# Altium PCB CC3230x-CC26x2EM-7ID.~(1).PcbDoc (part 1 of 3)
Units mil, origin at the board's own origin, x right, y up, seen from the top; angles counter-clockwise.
Board outline 2700 x 2300 mil, 4 copper layers (Top Layer, GND, PWR, Bottom Layer), stack 48.84 mil thick; 159 components, 102 nets, 511 pads, 818 vias.
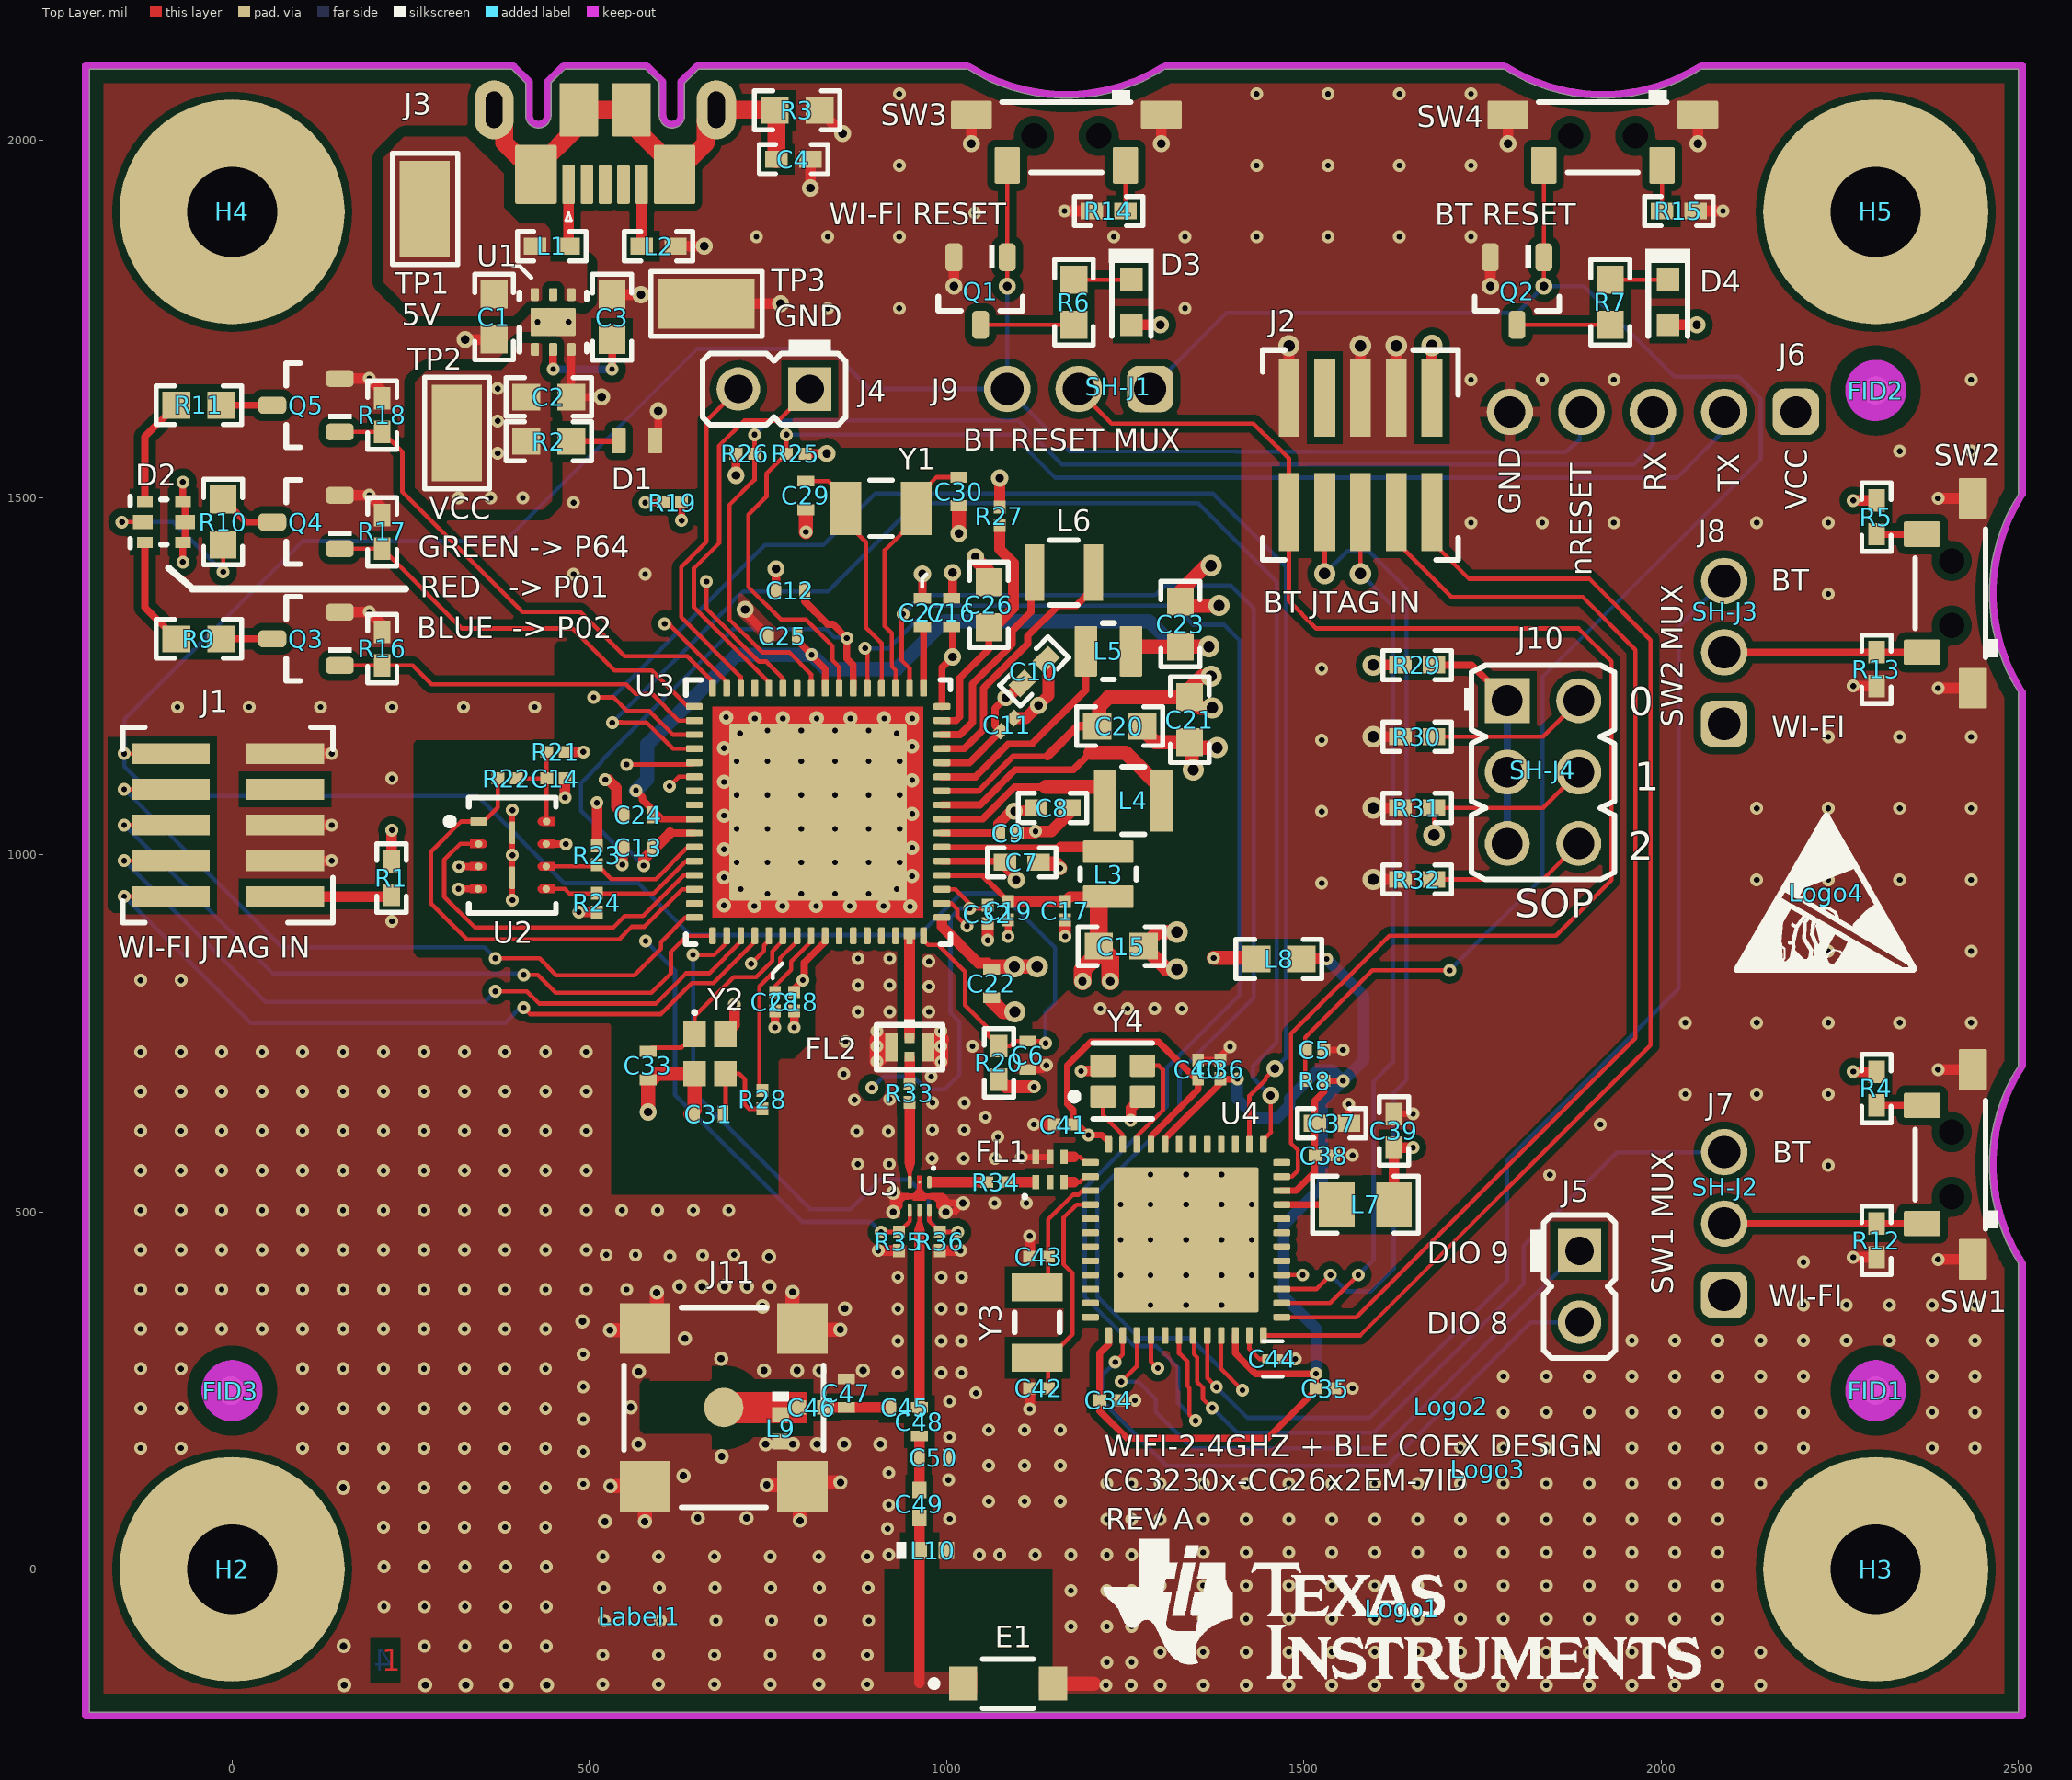
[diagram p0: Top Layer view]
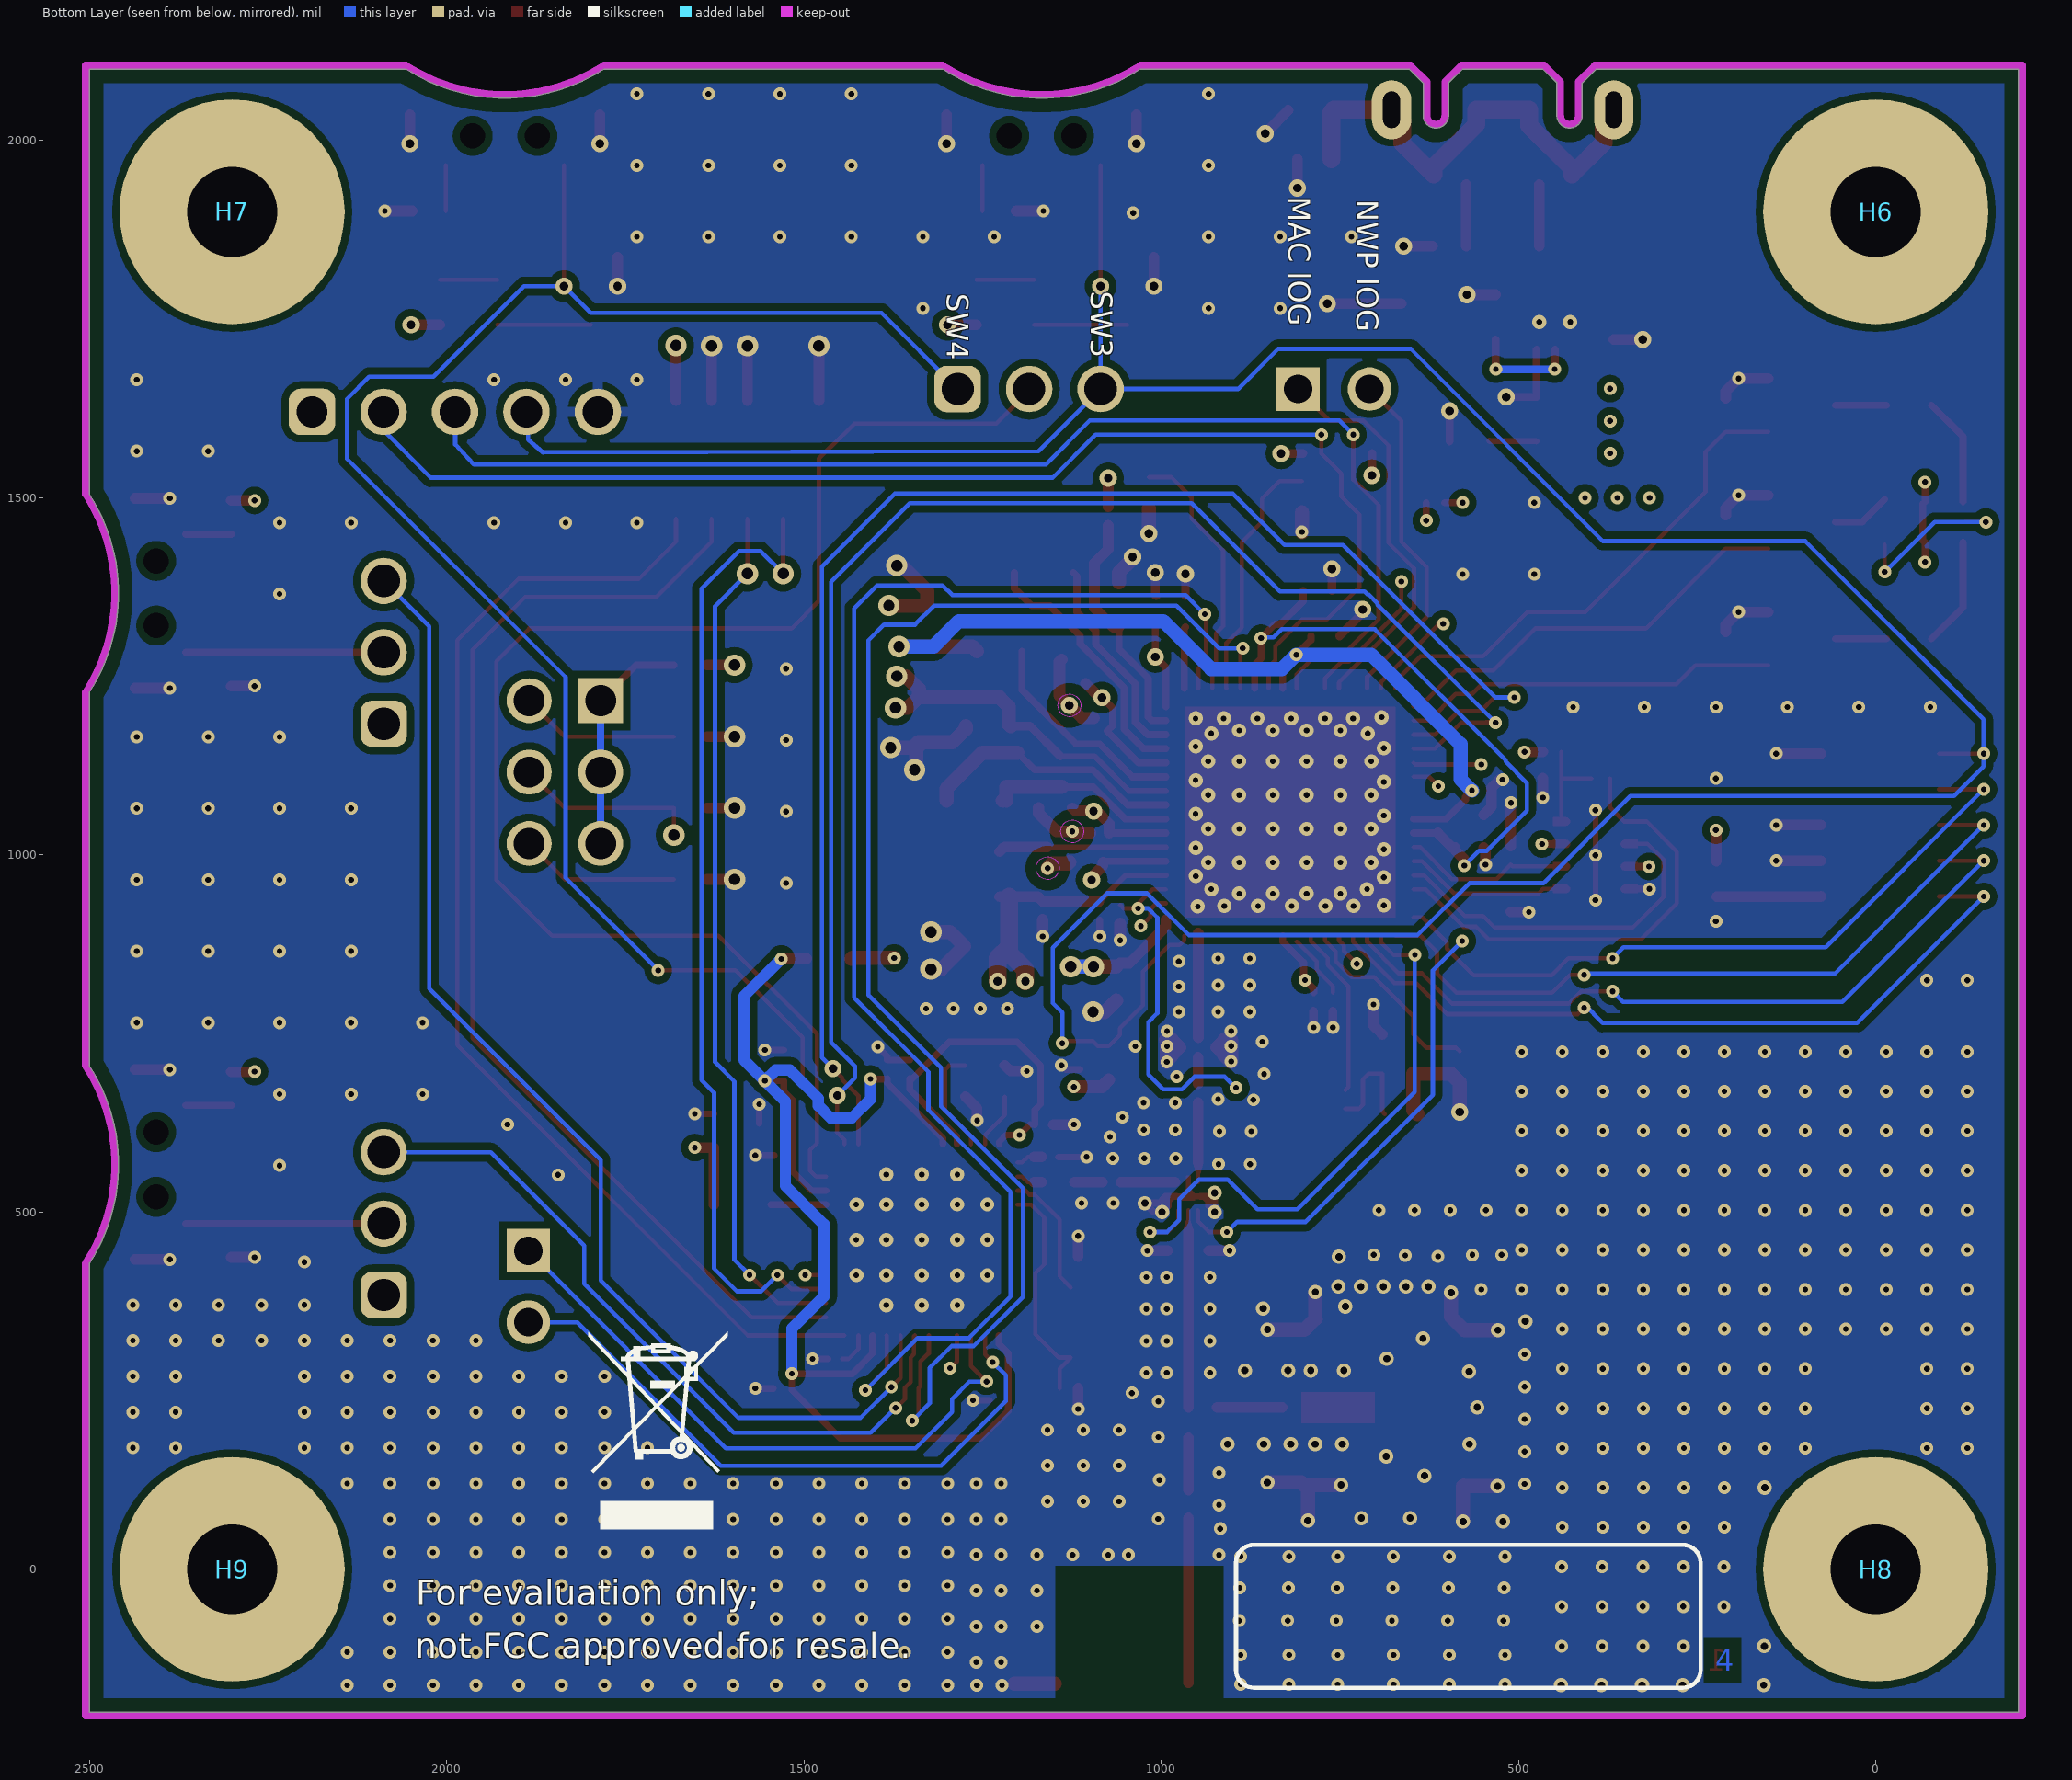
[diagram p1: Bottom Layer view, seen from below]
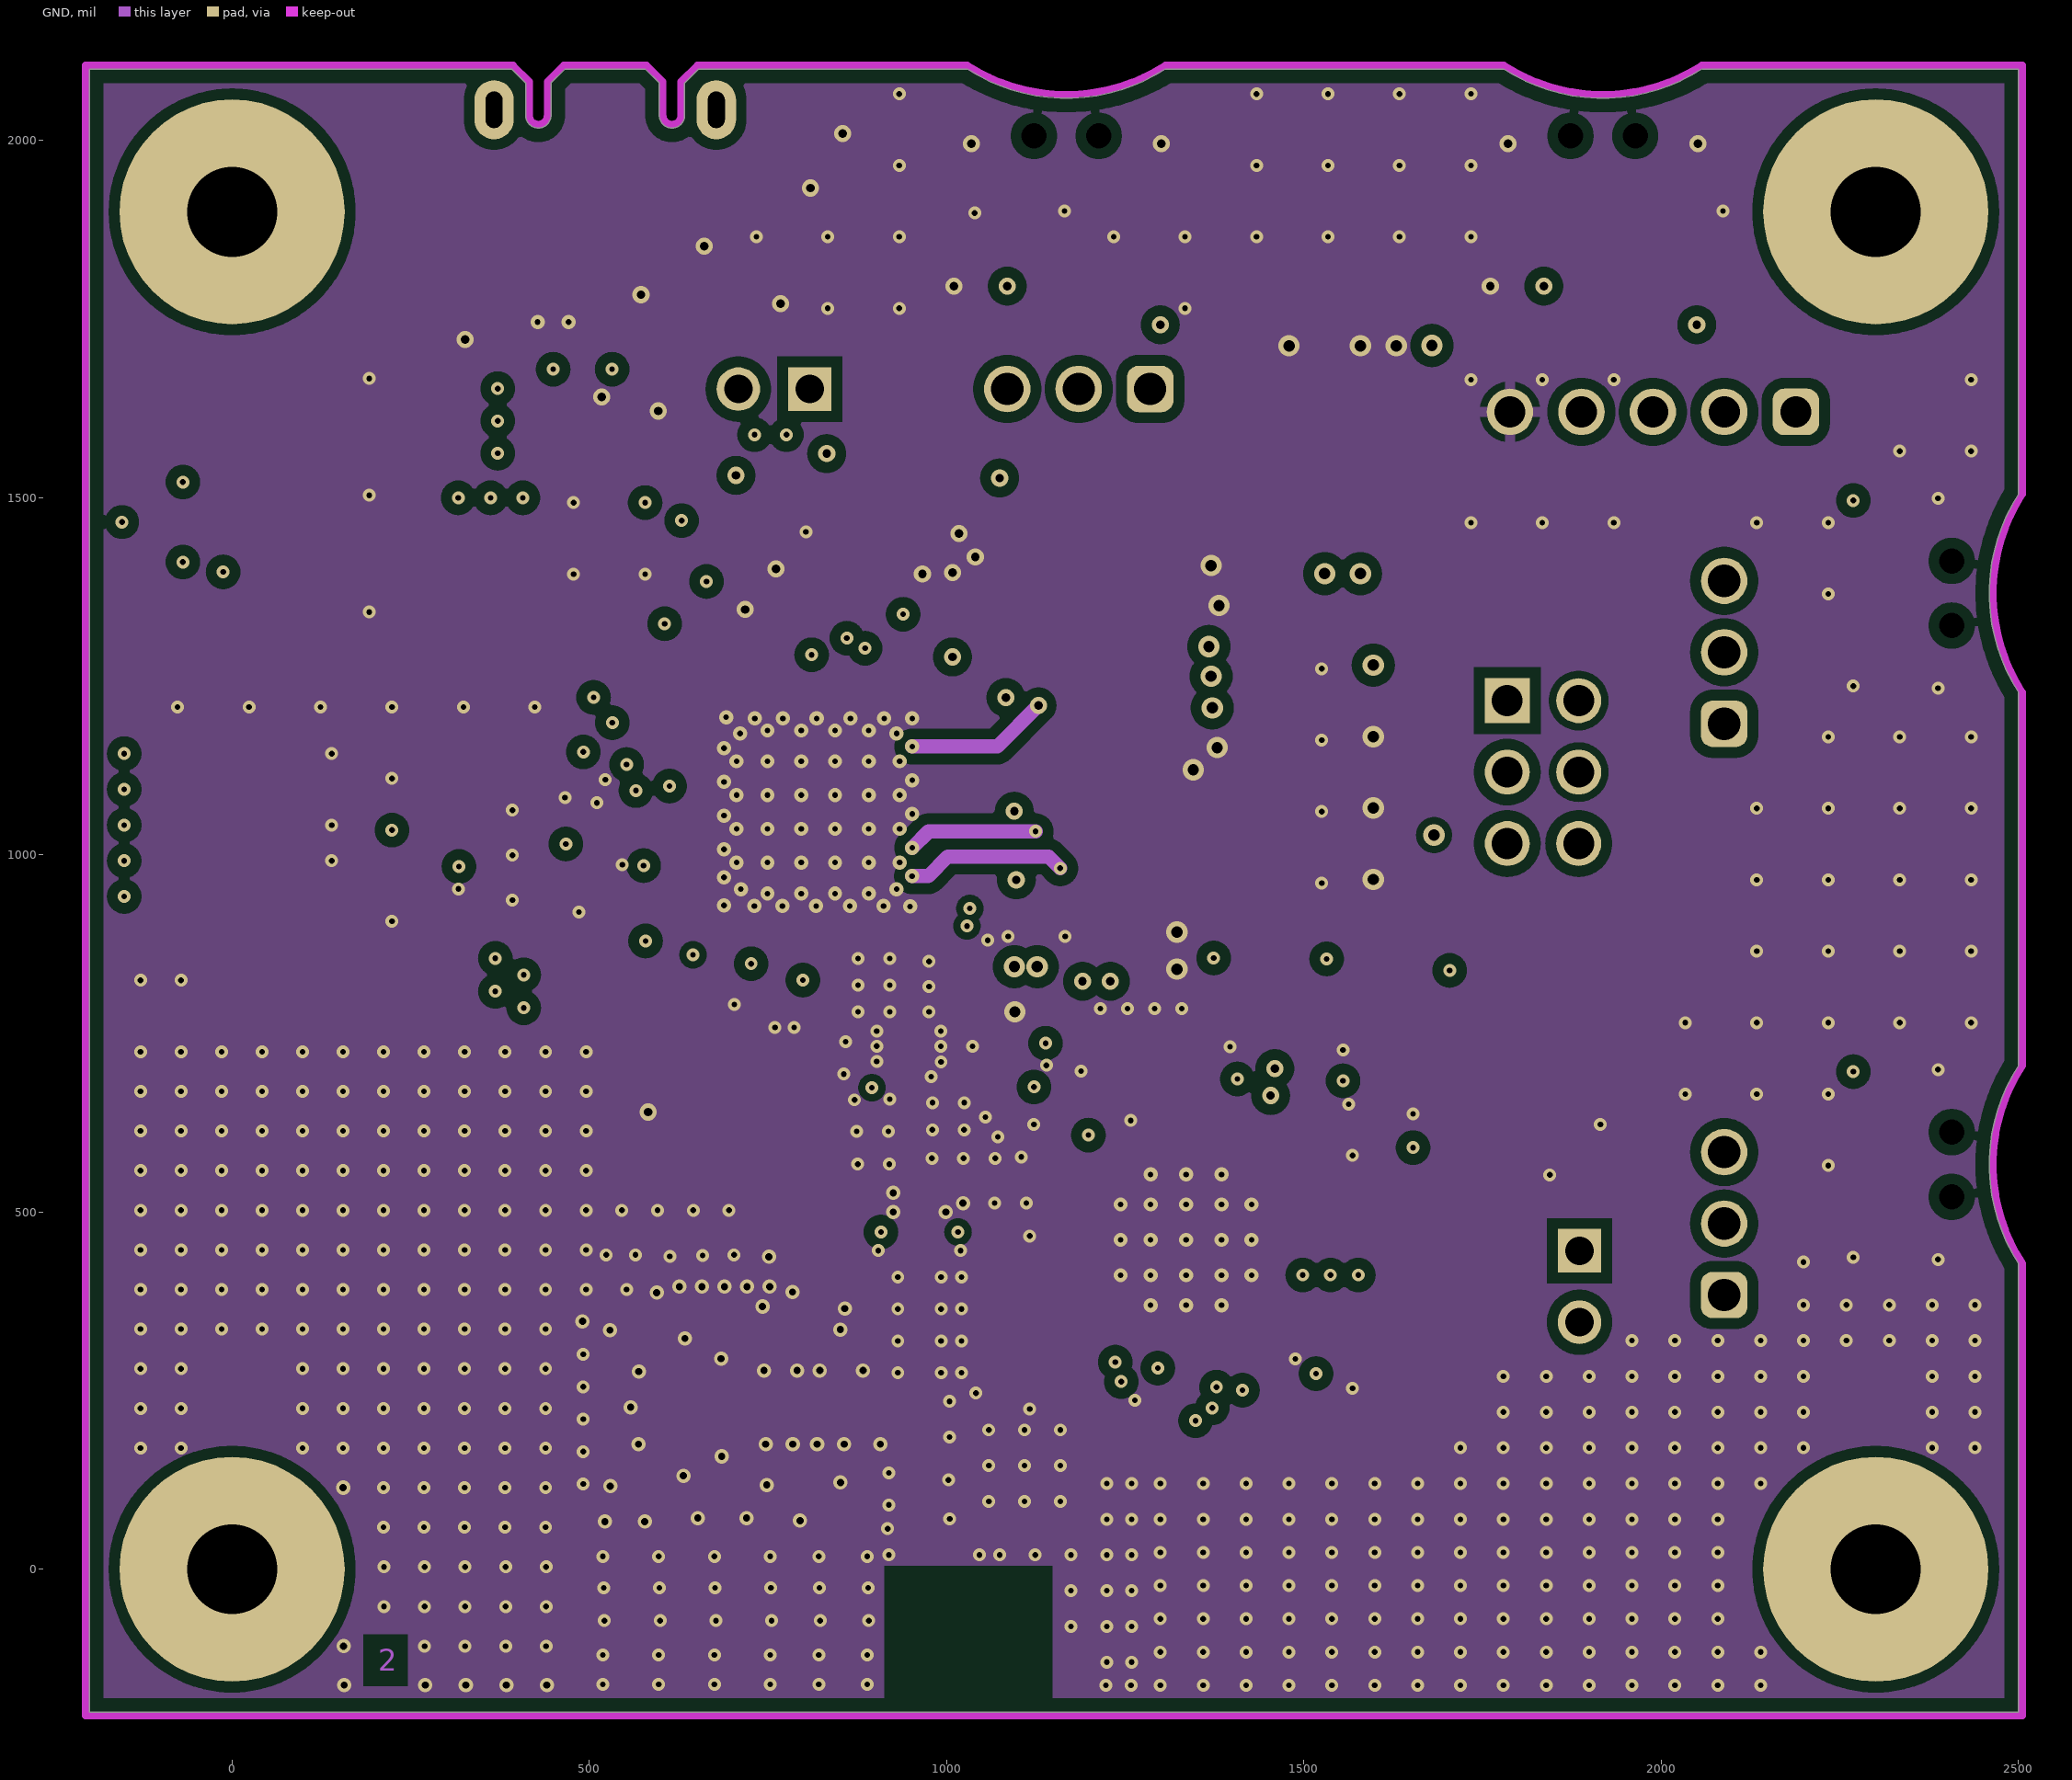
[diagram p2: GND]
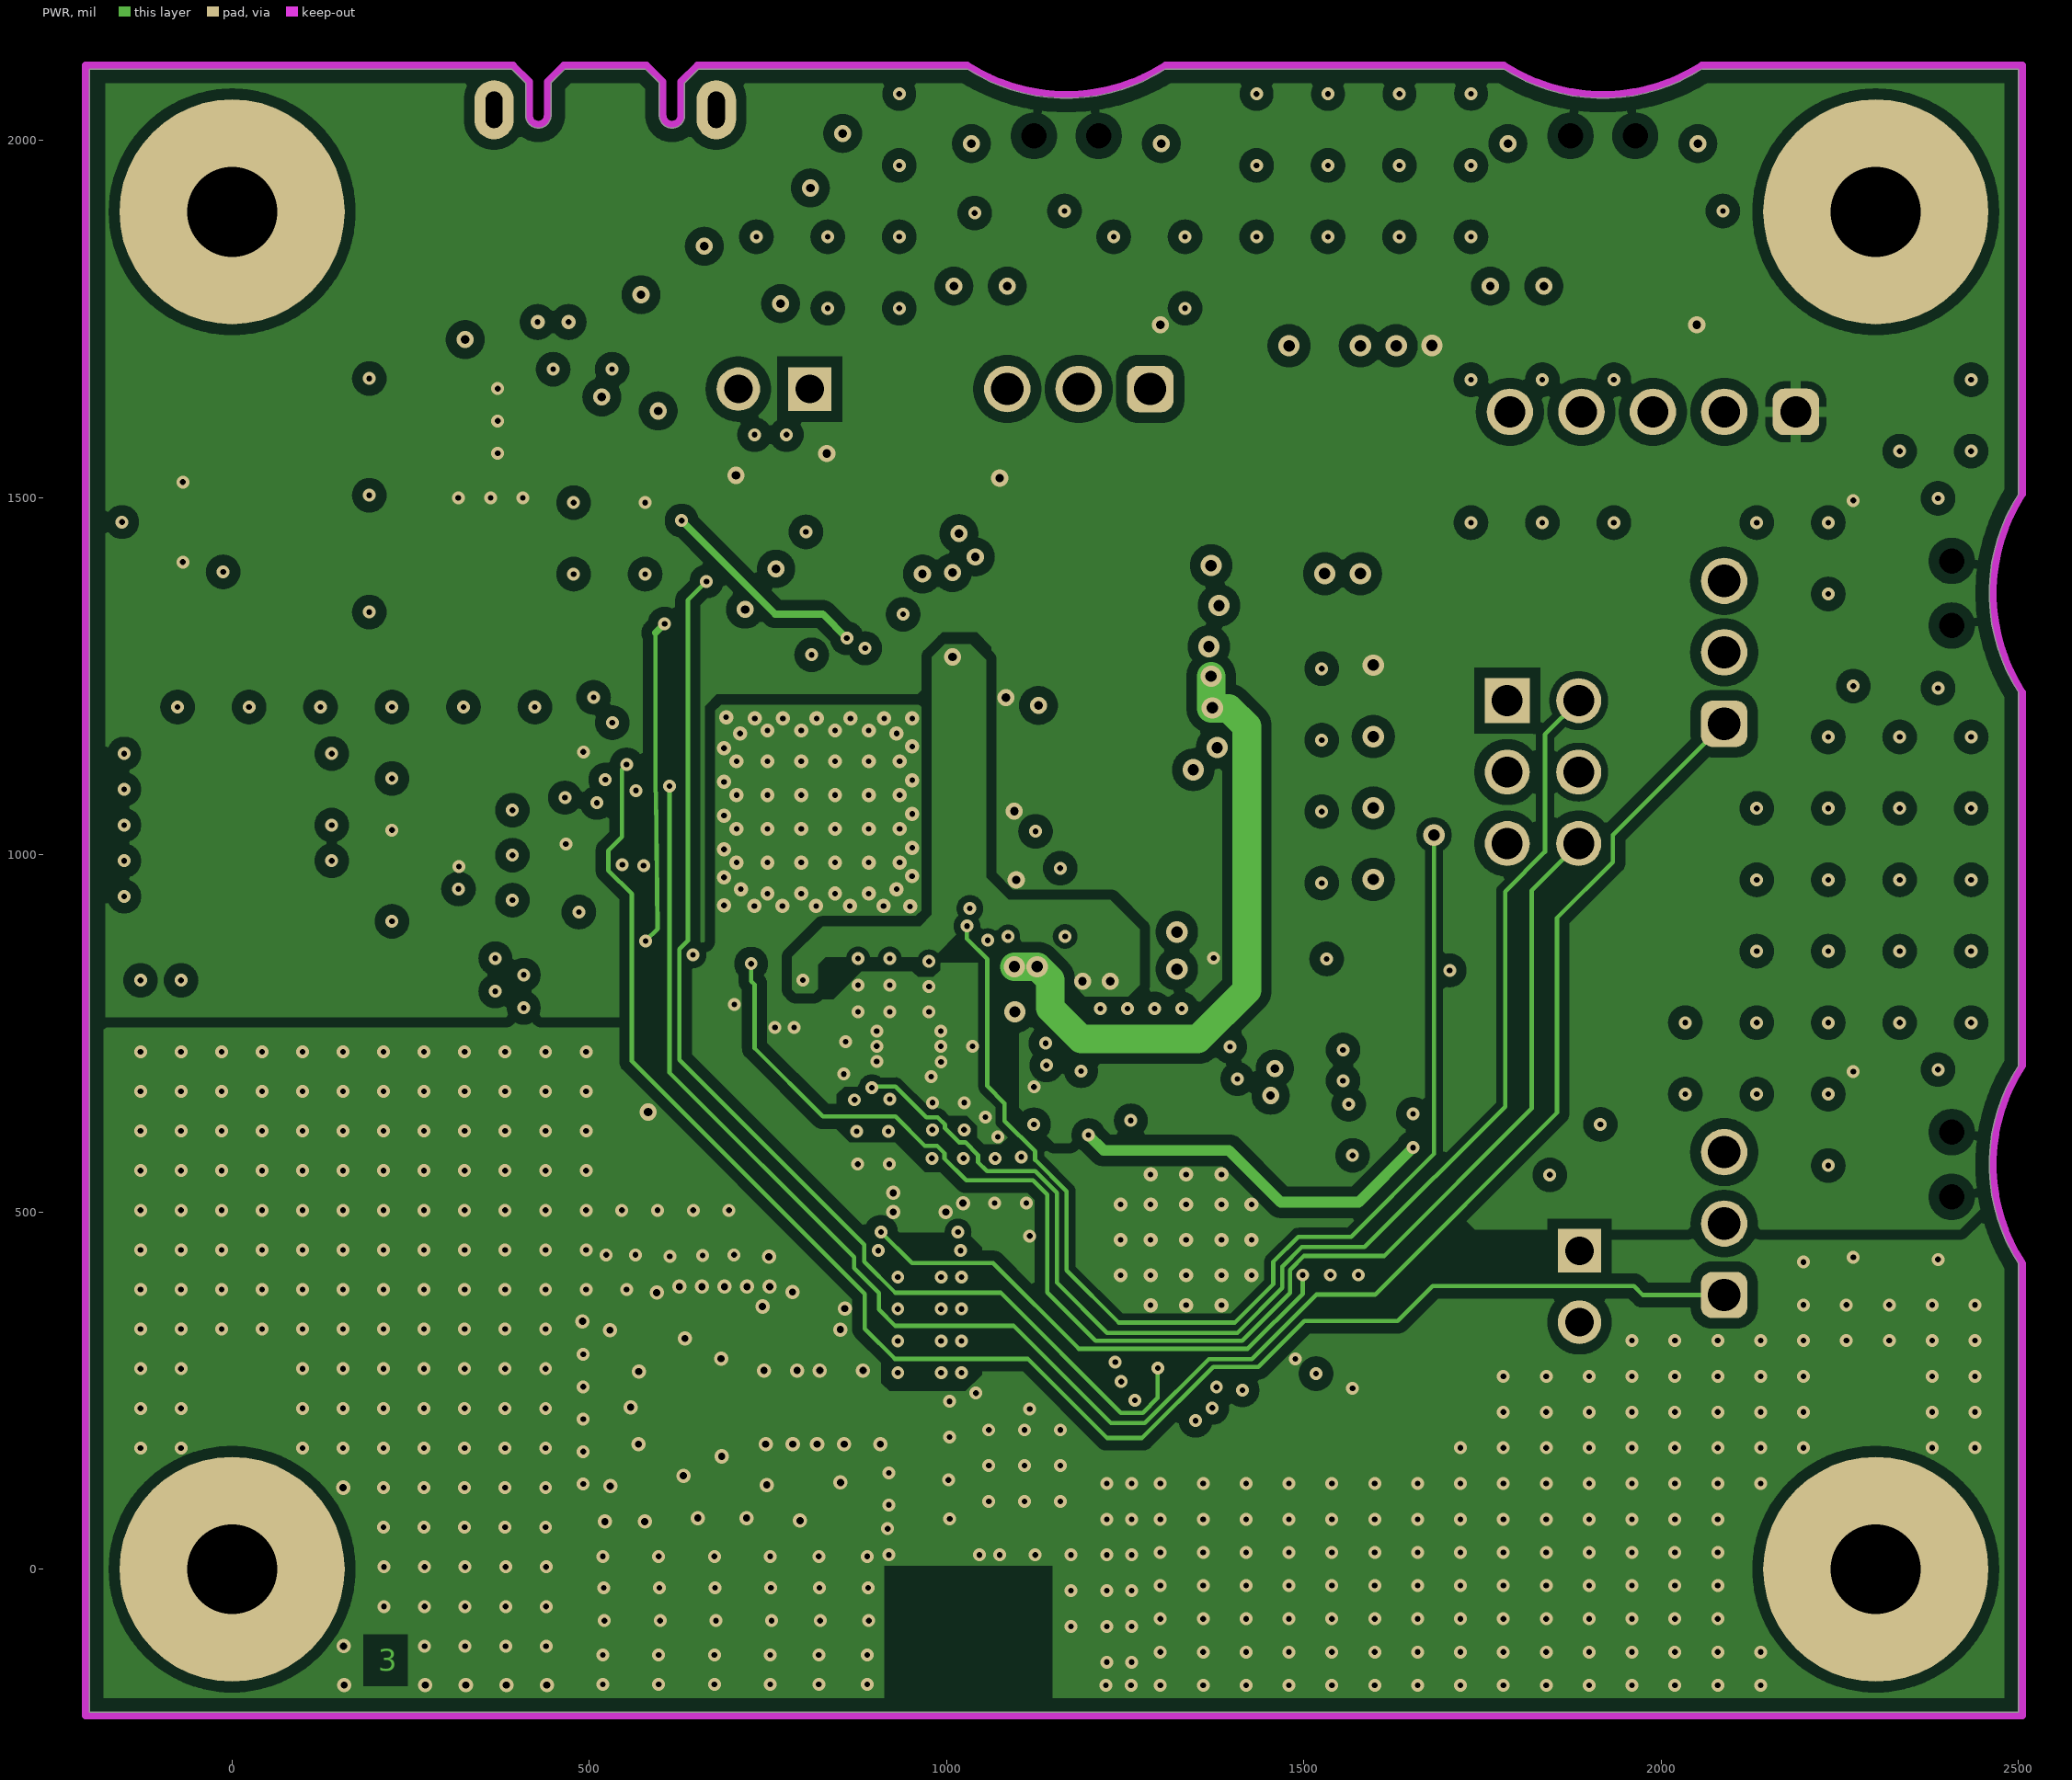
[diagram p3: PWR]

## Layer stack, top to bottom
Top Solder: solder mask 0.8, Solder Resist, Dk 4.1
Top Layer: signal copper 1.69
Dielectric1: core 9.3, FR-4 High Tg, Dk 3.9
GND: signal copper 1.42
Dielectric2: prepreg 24.02, FR-4 High Tg, Dk 4.24
PWR: signal copper 1.42
Dielectric3: core 9.3, FR-4 High Tg, Dk 3.9
Bottom Layer: signal copper 1.69
Bottom Solder: solder mask 0.8, Solder Resist, Dk 4.1

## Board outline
410.78,2035.04 ccw(c428.5,2035.04) 446.21,2035.04 446.21,2080.32 465.9,2100 578.1,2100 597.79,2080.32 597.79,2035.04 ccw(c615.51,2035.04) 633.22,2035.04 633.22,2080.32 652.91,2100 1028.76,2100 ccw(c1167.36,2313.24) 1305.95,2100 1779.55,2100 ccw(c1918.15,2313.24) 2056.74,2100 2500,2100 2500,1504.74 2499.99,1504.74 ccw(c2713.23,1366.14) 2499.99,1227.55 2499.99,705.13 ccw(c2713.23,566.54) 2499.99,427.95 2500,427.95 2500,-200 -200,-200 -200,2100 391.1,2100 410.78,2080.32

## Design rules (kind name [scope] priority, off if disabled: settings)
AcuteAngle [All] p1: minimum=4.50000000000000E+0001 checktracksonly=FALSE
AssemblyTestPointUsage [All] p1: valid=2
Clearance Clearance_BottomKO [iskeepout and OnBottomLayer vs InPoly] p1: gap=15 ignorepadtopadclearanceinfootprint=FALSE
Clearance Clearance_Keepouts [IsKeepOut] p2: gap=20 ignorepadtopadclearanceinfootprint=FALSE
Clearance Clearance_Via_Room [WithinRoom('RoomVia') and IsVia vs inpoly] p3: gap=6 ignorepadtopadclearanceinfootprint=FALSE
Clearance Clearance_2 [inpoly and OnLayer('PWR') and InNet('VDD_ANA') vs isvia and InNet('GND')] p4: gap=8 ignorepadtopadclearanceinfootprint=FALSE
Clearance Clearance_1 [InNet('WiFi_P18_GPIO_28') or InNet('WiFi_P15_GPIO_22') or InNet('WiFi_P34_SOP1') or InNet('WiFi_P35_SOP0') vs Inpoly] p5: gap=10 ignorepadtopadclearanceinfootprint=FALSE
Clearance Clearance_gnd [(OnLayer('gnd') or OnLayer('PWR')) AND INPOLY] p6: gap=15 ignorepadtopadclearanceinfootprint=FALSE
Clearance Clearance_Poly2Poly [InPolygon vs InPolygon] p7: gap=15 ignorepadtopadclearanceinfootprint=FALSE
Clearance Clearance_Poly_All [InPolygon] p8: gap=10 ignorepadtopadclearanceinfootprint=FALSE
Clearance [All] p9: gap=5.9 ignorepadtopadclearanceinfootprint=FALSE except(0: Arc-Hole Track-Hole SMDPad-Hole THPad-Hole Via-Hole Fill-Hole Poly-Hole Region-Hole Text-Hole; 3.9: Arc-SMDPad Track-SMDPad; 4.8: Arc-Fill Arc-Poly Arc-Region Track-Fill Track-Poly Track-Region SMDPad-Fill SMDPad-Poly SMDPad-Region; 5: Arc-Arc Arc-Track Track-Track; 5.6: Arc-Via Track-Via; 6.8: Via-Via; 7: Arc-THPad Track-THPad SMDPad-SMDPad SMDPad-THPad SMDPad-Via THPad-THPad THPad-Via)
ComponentClearance ComponentClearance_ScrewToNut [(HasFootprint('NY PMS 440 0025 PH')) vs (HasFootprint('Keystone_1902C'))] p1: gap=5 collisioncheckmode=3 verticalgap=10 showdistances=FALSE
ComponentClearance [All] p2: gap=10 collisioncheckmode=3 verticalgap=10 showdistances=FALSE
DiffPairsRouting [All] p1: maxlimit=100 minlimit=10 mostfreqgap=10 toplayer_minwidth=15 toplayer_maxwidth=15 toplayer_prefwidth=15 midlayer1_minwidth=15 midlayer1_maxwidth=15 midlayer1_prefwidth=15 midlayer2_minwidth=15 midlayer2_maxwidth=15 midlayer2_prefwidth=15 bottomlayer_minwidth=15 bottomlayer_maxwidth=15 bottomlayer_prefwidth=15 maxuncoupledlength=1000
FabricationTestPointUsage TestPointUsage [All] p1: valid=2 allowmultiple=FALSE
FabricationTestpoint Testpoint [All] p1: side=3 testpointundercomponent=TRUE minsize=40 maxsize=100 preferedsize=60 minholesize=0 maxholesize=40 preferedholesize=32 testpointgrid=1 allowsidetop=TRUE allowsidebottom=TRUE usegrid=TRUE gridtolerance=0.01
FanoutControl Fanout_LCC [IsLCC] p1: bgadir=Out bgaviamode=Centered fanoutstyle=Auto fanoutdirection=Alternating viagrid=1 // Fanout_LCC (Default Rule)
FanoutControl Fanout_BGA [IsBGA] p2: bgadir=Out bgaviamode=Centered fanoutstyle=Auto fanoutdirection=Alternating viagrid=1 // Fanout_BGA (Default Rule)
FanoutControl Fanout_Default [All] p4: bgadir=Out bgaviamode=Centered fanoutstyle=Auto fanoutdirection=Alternating viagrid=1 // Fanout_Default (Default Rule)
FanoutControl Fanout_Small [(CompPinCount < 5)] p5: bgadir=Out bgaviamode=Centered fanoutstyle=Auto fanoutdirection=OutThenIn viagrid=1 // Fanout_Small (Default Rule)
HoleSize [All] p1: absolutevalues=TRUE maxlimit=251 minlimit=7.87 maxpercent=80.000 minpercent=20.000
MinimumAnnularRing MinimumAnnularRing_ThermalPadVias [IsVia] p1: minimumring=5
MinimumAnnularRing [All] p2: minimumring=7.5
MinimumSolderMaskSliver MinimumSolderMaskSliver_Logo [InComponentClass('Logo') vs InComponentClass('Logo')] p1: minsoldermaskwidth=0.7
MinimumSolderMaskSliver [All] p2: minsoldermaskwidth=3
PlaneConnect [All] p1: planeconnectstyle=Relief reliefexpansion=10 reliefentries=4 reliefconductorwidth=10 reliefairgap=10
PolygonConnect [All] p1: thpad.connectstyle=Relief thpad.reliefconductorwidth=15 thpad.reliefentries=4 thpad.polygonreliefangle="90 Angle" thpad.airgapwidth=10 smdpad.connectstyle=Direct smdpad.reliefconductorwidth=10 smdpad.reliefentries=4 smdpad.polygonreliefangle="90 Angle" smdpad.airgapwidth=10 via.connectstyle=Direct via.reliefconductorwidth=10 via.reliefentries=4 via.polygonreliefangle="90 Angle" via.airgapwidth=10
RoomDefinition COEX_Power_Reset_Interfaces [InComponentClass('COEX_Power_Reset_Interfaces')] p1: confinementstyle=ConfineIn formatcopy=TRUE lockcomponents=FALSE outline 634.22,901.6 986.77,901.6 986.77,657 634.22,657
RoutingVias ThermalPadVias [IsVia and InAnyComponent] p1: holewidth=7.87 width=19.68 viastyle="Through Hole" minholewidth=7.87 minwidth=19.68 maxholewidth=12.99 maxwidth=23.62
RoutingVias [All] p2: holewidth=16 width=34 viastyle="Through Hole" minholewidth=7.87 minwidth=18 maxholewidth=40 maxwidth=65
SilkToBoardRegionClearance [Not ((IsComment or IsDesignator) And (Hide <> 'False')) and not InRegion(1000,500,4000,800)] p1:
SilkToSilkClearance SilkToSilkClearance_Pb-FreeLogo [(HasFootprint('Pb-Free_Overlay_Medium') OR HasFootprint('Pb-Free_Overlay_Small')) vs (HasFootprint('Pb-Free_Overlay_Medium') OR HasFootprint('Pb-Free_Overlay_Small'))] p1: silktosilkclearance=0
SilkToSilkClearance [All] p2: silktosilkclearance=4
SilkToSolderMaskClearance SilkToComonentPadClearance [IsPad and InAnycomponent] p1: minsilkscreentomaskgap=5 clearancetoexposedcopper=TRUE
SilkToSolderMaskClearance "Silk to Solder Mask Opening" [All] p2: minsilkscreentomaskgap=4 clearancetoexposedcopper=FALSE
SolderMaskExpansion [All] p1: expansion=0
Width [All] p1: maxlimit=100 minlimit=5.9 preferedwidth=10 minimp=50.000000 maximp=50.000000 favimp=50.000000 checkconnectedcopper=TRUE
15 further rules are at their usual default settings.

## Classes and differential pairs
component class Logo: Logo2
component class Label: Label1
component class AssemblyNote: ZZ1 ZZ2 ZZ3 ZZ4
component class FiducialMark: FID1 FID2 FID3
component class COEX_Hardware: FID1 FID2 FID3 H2 H3 H4 H5 H6 H7 H8 H9 Label1 Logo1 Logo2 Logo3 Logo4 SH-J1 SH-J2 SH-J3 SH-J4 ZZ1 ZZ2 ZZ3 ZZ4
component class "Mounting Holes": H1 H2 H3 H4 H5
component class Header: J4 J5 J6 J8 J9 J10
component class COEX_Power_Reset_Interfaces: C1 C2 C3 C4 C5 D1 D2 D3 D4 J1 J2 J3 J4 J5 J6 J9 J10 L1 L2 Q1 Q2 Q3 Q4 Q5 R2 R3 R4 R5 R6 R7 R8 R10 R11 R12 R16 R17 R18 R35 SW1 SW2 SW3 SW4 TP1 TP2 TP3 U1
component class COEX_CC3230S_EngineArea: C6 C7 C8 C9 C10 C11 C12 C13 C14 C15 C16 C17 C18 C19 C20 C21 C22 C23 C24 C25 C26 C27 C28 C29 C30 C31 C32 C33 J10 L3 L4 L5 L6 R17 R19 R20 R21 R23 R24 R25 R26 R27 R28 R29 R30 R31 R32 U2 U3 Y1 Y2
component class COEX_CC2642R_EngineArea: C5 C34 C35 C36 C37 C38 C39 C40 C41 C42 C44 FL1 L7 L8 R? U4 Y3 Y4
component class COEX_AntennaRFSection: C45 C46 C47 C48 C49 C50 E1 FL2 J10 L9 L10 R8 R33 R35 R36 U5
component class Shunt: SH-J1 SH-J2 SH-J3 SH-J4

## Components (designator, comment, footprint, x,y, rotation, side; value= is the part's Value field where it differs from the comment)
C1 "GRM188R71E105KA12D" 0603 366.53,1752.71 r270 top value=1uF
C2 "GRM188R71E105KA12D" 0603 443.26,1640.84 r0 top value=1uF
C3 "06031C102JAT2A" 0603 531.79,1752.52 r90 top locked value=1000pF
C4 "C1005X7R1C103K050BA" 0402 785.5,1973.8 r0 top locked value=0.01uF
C5 "GRM033Z71C104KE14D" 0201 1514.87,726.94 r0 top value=0.1uF
C6 "0402B103K500CT" 0402S 1113.53,719.34 r270 top value=0.01uF
C7 "CMP-0064972-2" 0402 1105,989.5 r0 top locked value=4.7uF
C8 "CMP-0064972-2" 0402 1147.91,1065.69 r0 top locked value=4.7uF
C9 "GJM0335C1ER60BB01D" 0201_033 1085.79,1030.47 r0 top locked value=0.6pF
C10 "CMP-0064972-2" 0402 1122.32,1256.71 r45 top locked value=4.7uF
C11 "GJM0335C1ER50BB01D" 0201_033 1084.87,1182.18 r45 top locked value=0.5pF
C12 "CL05B104KO5NNNC" 0402S 781.16,1369.99 r180 top locked value=0.1uF
C13 "CL05B104KO5NNNC" 0402S 568.62,1010 r180 top locked value=0.1uF
C14 "GRM033Z71C104KE14D" 0201 453.03,1107.03 r0 top value=0.1uF
C15 "CMP-0064953-4" 0603 1244,872 r0 top locked value=10uF
C16 "CL05B104KO5NNNC" 0402S 1007,1339 r90 top locked value=0.1uF
C17 "GJM0335C1ER20BB01D" 0201_033 1165.68,921.74 r270 top locked value=0.2pF
C18 "CL03A104KP3NNNC" 0201 786.58,794.26 r270 top value=0.1uF
C19 "GJM0335C1ER60BB01D" 0201_033 1085.88,921.74 r270 top locked value=0.6pF
C20 "CMP-0064952-4" 0603 1242,1180 r0 top locked value=22uF
C21 "CMP-0064952-4" 0603 1340,1189 r270 top locked value=22uF
C22 "CL05A105MP5NNNC" 0402S 1062.64,819.79 r270 top locked value=1uF
C23 "CMP-0064953-4" 0603 1327,1323 r90 top locked value=10uF
C24 "CL05B104KO5NNNC" 0402S 568.62,1056 r180 top locked value=0.1uF
C25 "CL05B104KO5NNNC" 0402S 770.4,1306.4 r180 top locked value=0.1uF
C26 "CMP-0064953-4" 0603 1059,1350 r90 top locked value=10uF
C27 "CL05B104KO5NNNC" 0402S 966,1339 r90 top locked value=0.1uF
C28 "CMP-0009655-3" 0201 759.69,794.26 r270 top value=0.1uF
C29 "0402N100J500CT" 0402S 803,1502.95 r270 top locked value=10pF
C30 "0402N100J500CT" 0402S 1016.97,1508.62 r270 top locked value=10pF
C31 "0402N6R2C500CT" 0402S 666.89,637 r180 top locked value=6.2pF
C32 "GJM0335C1ER60BB01D" 0201_033 1057.24,916.74 r270 top value=0.6pF
C33 "0402N6R2C500CT" 0402S 582.17,705 r270 top locked value=6.2pF
C34 "GRM033Z71C104KE14D" 0201 1227.13,236.52 r0 top value=0.1uF
C35 "GRM033Z71C104KE14D" 0201 1529.82,253.06 r0 top value=0.1uF
C36 "GRM033Z71C104KE14D" 0201 1383.14,699.65 r90 top locked value=0.1uF
C37 "GRM155R60J226ME11D" 0402 1538.87,624.2 r0 top value=22uF
C38 "GRM033Z71C104KE14D" 0201 1528.24,579.25 r0 top value=0.1uF
C39 "GRM155R60J226ME11D" 0402 1625.87,613.75 r90 top value=22uF
C40 "GRM033Z71C104KE14D" 0201 1351.65,699.65 r90 top locked value=0.1uF
C41 "GRM033Z71C104KE14D" 0201 1163.84,622.46 r180 top locked value=0.1uF
C42 "C0603C0G1E120J030BA" 0201_033 1129.12,253.28 r180 top value=12pF
C43 "C0603C0G1E120J030BA" 0201_033 1129.12,437.63 r180 top value=12pF
C44 "JMK063BC6105MP-F" FP-JMK063BC6105MP-F_0201-MFG 1456.21,294.44 r180 top
C45 "CMP-0006495-2" 0402S 941.85,226.53 r180 top locked value=8.2pF
C46 "CMP-0006447-2" 0402L 811.01,226.4 r180 top value=2.2pF
C47 "CMP-0006426-2" 0402S 859.44,246.4 r90 top value=1pF
C48 "CMP-0006495-2" 0402S 961.85,206.53 r270 top locked value=8.2pF
C49 "CMP-0006447-2" 0402L 961.85,91.39 r270 top value=2.2pF
C50 "CMP-0006426-2" 0402S 981.85,156.39 r0 top value=1pF
D1 "19-217/R6C-AL1M2VY/3T" 19-217_R6C-AL1M2VY_3T_Red 566.46,1579.57 r0 top locked value=Red
D2 "EAST1616RGBA8" EAST1616_RGB -95.52,1465.84 r270 top value=RGB
D3 "150060YS75000" WL-SMCW_YELLOW 1258.42,1773.44 r270 top locked value=Yellow
D4 "150060YS75000" WL-SMCW_YELLOW 2009.21,1773.44 r270 top locked value=Yellow
E1 "AH316M245001-T" TAYO_AH316M 1085.71,-160 r0 top
FID1 "CMP-0077181-1" Fiducial10-20#1 2300,250 r90 top
FID2 "CMP-0077181-1" Fiducial10-20#1 2300,1650 r270 top
FID3 "CMP-0077181-1" Fiducial10-20#2 0,250 r90 top
FL1 "2450BM14G0011" Johanson_2450BM14G0011 1144.47,559.49 r90 top locked
FL2 "CMP-0002039-2" TDK_DEA202450BT-1294C1-H 948.07,730.46 r0 top value="1.02 dB"
H2 "NY PMS 440 0025 PH" "NY PMS 440 0025 PH" 0,0 r180 top locked
H3 "NY PMS 440 0025 PH" "NY PMS 440 0025 PH" 2300,0 r180 top locked
H4 "NY PMS 440 0025 PH" "NY PMS 440 0025 PH" 0,1900 r180 top locked
H5 "NY PMS 440 0025 PH" "NY PMS 440 0025 PH" 2300,1900 r180 top locked
H6 "Nut" Keystone_1902C 0,1900 r0 bottom locked
H7 "Nut" Keystone_1902C 2300,1900 r0 bottom locked
H8 "Nut" Keystone_1902C 0,0 r0 bottom locked
H9 "Nut" Keystone_1902C 2300,0 r0 bottom locked
J1 "FTSH-105-01-F-DV-K" Samtec_FTSH-105-01-x-DV-K -6.04,1041.65 r180 top locked
J2 "FTSH-105-01-F-DV-K" Samtec_FTSH-105-01-x-DV-K 1578.93,1559.75 r270 top
J3 "1051640001" Molex_1051640001 522,2100 r180 top
J4 "GBC02SAAN" Sullins_Gxx02SAAN 758.31,1651.91 r180 top locked
J5 "GBC02SAAN" Sullins_Gxx02SAAN 1885.45,395.74 r270 top
J6 "61300511121" Wurth_61300511121 1988.12,1620 r180 top
J7 "61300311121" WURTH_61300311121 2087.92,483.86 r90 top
J8 "61300311121" WURTH_61300311121 2087.92,1283.47 r90 top
J9 "61300311121" WURTH_61300311121 1184.68,1652.09 r180 top
J10 "61300621121" Wurth_61300621121 1834.35,1115.81 r0 top
J11 "CMP-0055832-1" Hustsan_SMA-10V21-TGG 687.93,226.39 r0 top locked
L1 "CMP-0003309-1" 0402 447.2,1851.8 r180 top value="10 ohm"
L2 "CMP-0003309-1" 0402 596.81,1851.8 r0 top value="10 ohm"
L3 "CMP-0058761-1" LQM2MPN_G0 1226,972.87 r90 top locked value=2.2uH
L4 "CMP-0058750-1" 1008 1261,1076 r180 top locked value=1uH
L5 "CMP-0058761-1" LQM2MPN_G0 1226.13,1285 r180 top locked value=2.2uH
L6 "CMP-0062710-1" MLP2520S-M 1164,1395 r0 top locked value=10uH
L7 "MLZ2012N6R8LT000" 0805_HV 1585.87,510.28 r0 top value=6.8uH
L8 "BLM18HE152SN1D" 0603 1464.74,854.35 r0 top value="1500 ohm"
L9 "LQG15HS3N9S02D" IND_LQG15H 767.58,197.44 r270 top value=3.9nH
L10 "LQG15HS3N9S02D" IND_LQG15H 980.55,26.39 r0 top value=3.9nH
Label1 "CMP-0003625-1" Label_650x200 570.15,-65.85 r0 top
Logo1 "Texas Instruments" TI_Stacked_Overlay_Small 1637.53,-55.51 r0 top
Logo2 "WEEE logo" WEEE_Minimum 1705.88,228.42 r180 top
Logo3 "FCC disclaimer" FCC_disclaimer_stacked 1756.84,140.19 r180 top locked
Logo4 "ESD Susceptible" ESD_Overlay_Medium 2230.55,946.28 r0 top
Q1 "CMP-0000755-1" SOT-23 1047.28,1789.18 r270 top value=50V
Q2 "CMP-0000755-1" SOT-23 1798.07,1789.18 r270 top value=50V
Q3 "BSS138" SOT-23 103.29,1302.37 r180 top value=50V
Q4 "BSS138" SOT-23 103.29,1465.84 r180 top value=50V
Q5 "BSS138" SOT-23 103.29,1629.3 r180 top value=50V
R1 "CRCW04021K00JNED" 0402 222.99,967.38 r270 top value=1.0k
R2 "CMP-0025765-4" 0603 443.26,1578.75 r0 top value=270
R3 "CMP-0025698-4" 0603 790.5,2042.15 r180 top locked value=100k
R4 "CMP-0026852-3" 0402 2301.1,672.84 r270 top value=1.0k
R5 "CMP-0026852-3" 0402 2301.1,1472.44 r270 top locked value=1.0k
R6 "CMP-0025765-4" 0603 1177.99,1773.44 r90 top locked value=270
R7 "CMP-0025765-4" 0603 1928.77,1773.44 r90 top locked value=270
R8 "RC0201JR-7D100KL" 0201 1514.87,683.63 r0 top value=100k
R9 "RC0603JR-07750RL" 0603 -46.63,1302.37 r180 top value=750
R10 "RC0603JR-07750RL" 0603 -12.58,1465.84 r270 top value=750
R11 "RC0603JR-07750RL" 0603 -46.63,1629.3 r180 top value=750
R12 "CMP-0026825-5" 0402 2301.1,460.24 r270 top value=10k
R13 "CMP-0026825-5" 0402 2301.1,1259.85 r270 top value=10k
R14 "CMP-0026656-1" 0402 1226.41,1901.11 r0 top locked value=100
R15 "CMP-0026656-1" 0402 2024.44,1901.11 r180 top value=100
R16 "CMP-0026823-3" 0402 209.96,1288.59 r90 top value=100k
R17 "CMP-0026823-3" 0402 209.96,1452.06 r90 top value=100k
R18 "CMP-0026823-3" 0402 209.96,1615.52 r90 top value=100k
R19 "CRCW02010000Z0ED" 0201 616,1492.99 r180 top locked value=0
R20 "CRCW0402100KJNED" 0402 1073.21,708.83 r270 top value=100k
R21 "CRCW02010000Z0ED" 0201 453.03,1144.04 r0 top value=0
R22 "RC0201JR-7D100KL" 0201 384.79,1107.03 r0 top value=100k
R23 "RC0201JR-7D100KL" 0201 510.53,999.28 r270 top value=100k
R24 "RC0201JR-7D100KL" 0201 510.53,933.01 r90 top value=100k
R25 "RC0201JR-7D100KL" 0201 788.68,1561.54 r0 top value=100k
R26 "RC0201JR-7D100KL" 0201 718.01,1561.54 r180 top value=100k
R27 "CRCW02010000Z0ED" 0201 1073.99,1474.02 r90 top locked value=0
R28 "CRCW02010000Z0ED" 0201 742.12,657.4 r90 top locked value=0
R29 "CRCW0402270RJNED" 0402 1658.32,1265.54 r180 top value=270
R30 "CRCW0402100KJNED" 0402 1658.32,1165.54 r0 top value=100k
R31 "CRCW0402100KJNED" 0402 1658.32,1065.54 r0 top value=100k
R32 "CRCW04022K70JNED" 0402 1658.32,965.54 r0 top value=2.7k
R33 "ERJ-1GE0R00C" 0201 948.07,666.37 r90 top value=0
R34 "ERJ-1GE0R00C" 0201 1069.15,541.78 r0 top value=0
R35 "RC0201JR-7D100KL" 0201 933.07,458.99 r90 top value=100k
R36 "RC0201JR-7D100KL" 0201 990.63,458.99 r90 top value=100k
SH-J1 "60900213421" Wurth_60900213421 1240.3,1655.53 r0 top
SH-J2 "60900213421" Wurth_60900213421 2089.67,535.35 r90 top
SH-J3 "60900213421" Wurth_60900213421 2089.68,1341.01 r90 top
SH-J4 "60900213421" Wurth_60900213421 1834.54,1118.82 r0 top
SW1 "CMP-0002328-1" SW_1188E 2392.57,566.54 r180 top
SW2 "CMP-0002328-1" SW_1188E 2392.57,1366.14 r180 top locked
SW3 "CMP-0002328-1" SW_1188E 1167.36,1992.58 r270 top
SW4 "CMP-0002328-1" SW_1188E 1918.15,1992.58 r270 top
TP1 "5015" Testpoint_Keystone_Miniature 269.58,1904.12 r90 top locked
TP2 "5015" Testpoint_Keystone_Miniature 314.28,1590.42 r90 top
TP3 "5015" Testpoint_Keystone_Miniature 663.85,1771.57 r0 top locked
U1 "TPS73733DRVR" DRV0006A 449.17,1745.82 r90 top
U2 "MX25R3235FZBIL0" FP-MX25R3235FZBIL0_USON8-MFG 392.2,999.49 r0 top
U3 "CC3230SM2RGKR" RGK0064B 820,1060 r0 top locked
U4 "CC2642R1FRGZR" RGZ0048A 1334.95,461.07 r0 top
U5 "RTC6608OSP" Richwave_RTC6608OSP 961.85,522.09 r270 top
Y1 "CMP-0004575-3" XTAL_ABS07 908,1485 r180 top locked
Y2 "8Y40072002" TXC_8Y 668.86,721.14 r0 top locked
Y3 "FC-135 32.7680KA-AG0" Epson_FC-135 1126.51,345.46 r90 top
Y4 "CX2016DB48000C0WPLA2" FP-CX2016DB48000C0WPLA2_SMD4-MFG 1246.35,683.28 r0 top locked
ZZ1 "This Assembly Note is for PCB labels only" AssemblyNoteLabel 3383.22,4392.05 r0 top locked
ZZ2 "These assemblies are ESD sensitive, ESD precautions shall be observed." AssemblyNote 3390.22,4263.05 r0 top locked
ZZ3 "These assemblies must be clean and free from flux and all contaminants. Use of no clean flux is not acceptable." AssemblyNote 3391.22,4124.05 r0 top locked
ZZ4 "These assemblies must comply with workmanship standards IPC-A-610 Class 2, unless otherwise specified." AssemblyNote 3389.22,3987.05 r0 top locked

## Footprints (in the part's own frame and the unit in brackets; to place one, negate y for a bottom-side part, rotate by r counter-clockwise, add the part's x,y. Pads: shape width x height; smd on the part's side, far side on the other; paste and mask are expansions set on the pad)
19-217_R6C-AL1M2VY_3T_Red [mm] "SMD, 2-Leads, Body 1.6x0.8mm"
  rrect20% 0.5x0.9 smd: 1(-0.65,0) 2(0.65,0)
  body extent -0.85,-0.45 0.85,0.45, height 0.5
0201 [mm] "Data from Kemet datasheet CC101_COM dated 7/28/11"
  rect 0.46x0.42 smd mask+0.048: 1(-0.33,0) 2(0.33,0)
  body extent -0.31,-0.16 0.31,0.16, height 0.26
0201_033 [mm] "SMD, 2-Leads, Height 0.33mm"
  rect 0.46x0.42 smd mask+0.048: 1(-0.33,0) 2(0.33,0)
  body extent -0.31,-0.16 0.31,0.16, height 0.33
0402 [mm] "0402 from SM-752 data"
  rect 0.8x0.6 smd: 1(-0.6,0) 2(0.6,0)
  silkscreen extent -1.22,-0.52 1.22,0.52, body extent -0.55,-0.3 0.55,0.3, height 0.6
0402L [mm] "0402 from SM-752 data"
  rect 0.6x0.5 smd: 1(-0.5,0) 2(0.5,0)
  body extent -0.55,-0.3 0.55,0.3, height 0.6
0402S [mil] "Based on C0402S footprint from PADS legacy"
  rect 15x24 smd: 1(-20,0) 2(20,0)
  body extent -22,-12 22,12, height 24
0603 [mm] "0603 from SM-752 data"
  rect 1x0.95 smd: 1(-0.8,0) 2(0.8,0)
  silkscreen extent -1.52,-0.69 1.52,0.69, body extent -0.87,-0.47 0.87,0.47, height 1
0805_HV [mil] "0805 with 30mil clearance between pads"
  rect 50x63 smd: 1(-40,0) 2(40,0)
  silkscreen extent -74,-40 74,40, body extent -43,-29 43,29, height 57
1008 [mm] "SMD, Body 2.5x2mm, Height 1.2mm"
  rect 0.8x2.2 smd: 1(-1,0) 2(1,0)
  silkscreen extent -0.4,-1.2 0.4,1.2, body extent -1.35,-1.1 1.35,1.1, height 1.2
AssemblyNote [mil] "Assembly Note"
AssemblyNoteLabel [mil] "Assembly Note for PCB Labels"
DRV0006A [mm] "SON, 6-Leads, Body 2x2mm, Pitch 0.65mm, Thermal Pad 1.6x1mm, TI Recommended"
  rrect33% 0.45x0.3 smd: 1(-0.975,0.65) 2(-0.975,0) 3(-0.975,-0.65) 4(0.975,-0.65) 5(0.975,0) 6(0.975,0.65)
  rrect14% 1x0.7 on Top Paste: 7(0,0.45) 7(0,-0.45)
  rrect10% 1x1.6 smd paste-0.5: 7(0,0)
  silkscreen extent -1.05,-1.2 1.05,1.2, body extent -1.05,-1.05 1.05,1.05, height 0.81
EAST1616_RGB [mm] "SMD, 6-Leads, Body 1.6x1.6mm"
  rect 0.4x0.55 smd: 1(-0.725,0.675) 2(-0.725,-0.675) 5(0.725,0.675) 6(0.725,-0.675)
  rect 0.5x0.7 smd: 3(0,0.75) 4(0,-0.75)
  silkscreen extent -0.9,-1.2 0.9,0.1, body extent -0.8,-0.8 0.8,0.8, height 0.5
Epson_FC-135 [mm] "SMD, 2-Leads, Body 3.2x1.5mm"
  rect 1x1.8 smd: 1(-1.25,0) 2(1.25,0)
  silkscreen extent -0.35,-0.8 0.35,0.8, body extent -1.65,-0.8 1.65,0.8, height 0.9
ESD_Overlay_Medium [mil]
  silkscreen extent -127,-109 125,110
FCC_disclaimer_stacked [mil]
Fiducial10-20#1 [mm]
  round 1 smd mask+0.5: 1(0,0)
  Top Layer keep-out circle w1.178: c0,0 r0.5
Fiducial10-20#2 [mm]
  round 1 smd mask+0.5: 1(0,0.053)
  Top Layer keep-out circle w1.178: c0,0 r0.5
FP-CX2016DB48000C0WPLA2_SMD4-MFG [mm]
  rrect13% 0.9x0.8 smd paste+0 mask+0: 1(-0.7,-0.55) 2(0.7,-0.55) 3(0.7,0.55) 4(-0.7,0.55)
  silkscreen extent -1.85,-1.35 1.05,1.35, body extent -1.25,-1.05 1.25,1.05, height 0.25
FP-JMK063BC6105MP-F_0201-MFG [mm]
  rrect40% 0.25x0.325 smd paste+0 mask+0: 1(-0.25,0) 2(0.25,0)
  silkscreen extent -0.35,-0.63 0.35,0.63, body extent -0.48,-0.3 0.48,0.3, height 0.25
FP-MX25R3235FZBIL0_USON8-MFG [mm]
  rrect33% 0.6x0.3 smd paste+0 mask+0: 1(-1.2,1.2)
  round 0.27 smd paste+0 mask+0: 2(-1.2,0.4) 3(-1.2,-0.4) 4(-1.215,-1.2) 5(1.2,-1.2) 6(1.2,-0.4) 7(1.2,0.4) 8(1.215,1.2)
  rrect50% 0.2x0.8 smd paste+0 mask+0: 9(0,0.8) 10(0,-0.8)
  Top Layer region: 1.5,1.05 1.05,1.05 0.993,1.061 0.944,1.094 0.911,1.143 0.9,1.2 0.9,1.2 0.911,1.257 0.944,1.306 0.993,1.339 1.05,1.35 1.05,1.35 1.5,1.35
  Top Layer region: 1.5,0.25 1.05,0.25 0.993,0.261 0.944,0.294 0.911,0.343 0.9,0.4 0.9,0.4 0.911,0.457 0.944,0.506 0.993,0.539 1.05,0.55 1.05,0.55 1.5,0.55
  Top Layer region: 1.5,-0.55 1.05,-0.55 0.993,-0.539 0.944,-0.506 0.911,-0.457 0.9,-0.4 0.9,-0.4 0.911,-0.343 0.944,-0.294 0.993,-0.261 1.05,-0.25 1.05,-0.25 1.5,-0.25
  Top Layer region: 1.5,-1.35 1.05,-1.35 0.993,-1.339 0.944,-1.306 0.911,-1.257 0.9,-1.2 0.9,-1.2 0.911,-1.143 0.944,-1.094 0.993,-1.061 1.05,-1.05 1.05,-1.05 1.5,-1.05
  Top Layer region: -1.5,-1.05 -1.05,-1.05 -0.993,-1.061 -0.944,-1.094 -0.911,-1.143 -0.9,-1.2 -0.9,-1.2 -0.911,-1.257 -0.944,-1.306 -0.993,-1.339 -1.05,-1.35 -1.05,-1.35 -1.5,-1.35
  Top Layer region: -1.5,-0.25 -1.05,-0.25 -0.993,-0.261 -0.944,-0.294 -0.911,-0.343 -0.9,-0.4 -0.9,-0.4 -0.911,-0.457 -0.944,-0.506 -0.993,-0.539 -1.05,-0.55 -1.05,-0.55 -1.5,-0.55
  Top Layer region: -1.5,0.55 -1.05,0.55 -0.993,0.539 -0.944,0.506 -0.911,0.457 -0.9,0.4 -0.9,0.4 -0.911,0.343 -0.944,0.294 -0.993,0.261 -1.05,0.25 -1.05,0.25 -1.5,0.25
  silkscreen extent -2.35,-2.05 1.55,2.05, body extent -1.65,-2.15 1.65,2.15, height 0.25
Hustsan_SMA-10V21-TGG [mm] "SMD, 4-Leads, Body 7.1x7.1mm"
  round 1.4 smd: 1(0,0)
  rect 1.8x1.8 smd: 2(-2.8,2.8) 3(-2.8,-2.8) 4(2.8,-2.8) 5(2.8,2.8)
  silkscreen extent -3.55,-3.55 3.55,3.55, body extent -3.55,-3.55 3.55,3.55, height 10.72
IND_LQG15H [mm] "MuRata"
  rect 0.55x0.6 smd: 1(-0.475,0) 2(0.475,0)
  silkscreen extent -1.3,-0.3 -0.95,0.3, body extent -0.52,-0.27 0.52,0.27, height 0.55
Johanson_2450BM14G0011 [mm] "SMD, 6-Leads, Body 1.6x0.8mm, Pitch 0.5mm"
  rect 0.5x0.25 smd: 1(-0.45,0.5) 2(-0.45,0) 3(-0.45,-0.5) 4(0.45,-0.5) 5(0.45,0) 6(0.45,0.5)
  silkscreen extent -1.02,0.84 -0.9,0.96, body extent -0.45,-0.85 0.45,0.85, height 0.71
Keystone_1902C [mil] "Hex Standoff, 4-40 threaded, nylon"
  round 1 on Mech4: 0(0,0)
  body extent -145,-126 146,126, height 501
Label_650x200 [mil] "Thermal Transfer Label"
  round 1 on Mech14: 0(0,0)
  body extent -325,-100 325,100, height 1
LQM2MPN_G0 [mm] "MuRata"
  rrect12% 0.8x1.8 smd: 1(-0.8,0) 2(0.8,0)
  silkscreen extent -0.2,-1 0.2,1, body extent -1.07,-0.87 1.07,0.87, height 1
MLP2520S-M [mm] "TDK"
  rect 0.7x2 smd: 1(-1.05,0) 2(1.05,0)
  silkscreen extent -0.5,-1.15 0.5,1.15, body extent -1.32,-1.07 1.32,1.07, height 1
Molex_1051640001 [mm] "Receptacle, USB 2.0, Micro B, 5 Pos, 0.65mm Pitch, R/A, SMT"
  rrect22% 0.45x1.38 smd: 1(1.3,4.11) 2(0.65,4.11) 3(0,4.11) 4(-0.65,4.11) 5(-1.3,4.11)
  rrect7% 1.475x2.1 smd: 6(-2.462,3.75) 11(2.462,3.75)
  rrect100% 1.4x2.1 hole 0.6 slot 1.3 at 90 deg: 7(-3.95,1.45) 10(3.95,1.45)
  rrect7% 1.375x1.9 smd: 8(-0.937,1.45) 9(0.937,1.45)
  silkscreen extent 1.2,5.1 1.4,5.4, body extent -4.1,-0.7 4.1,4.47, height 2.45
"NY PMS 440 0025 PH" [mm] "4-40 nylon screw and mounting hole"
  round 8 hole 3.2: 1(0,0)
  body extent -3.3,-3.3 3.3,3.3, height 2.69
RGK0064B [mm] "VQFN-64"
  rrect42% 0.6x0.24 smd: 1(-4.4,3.75) 2(-4.4,3.25) 3(-4.4,2.75) 4(-4.4,2.25) 5(-4.4,1.75) 6(-4.4,1.25) 7(-4.4,0.75) 8(-4.4,0.25) 9(-4.4,-0.25) 10(-4.4,-0.75) 11(-4.4,-1.25) 12(-4.4,-1.75) 13(-4.4,-2.25) 14(-4.4,-2.75) 15(-4.4,-3.25) 16(-4.4,-3.75) 33(4.4,-3.75) 34(4.4,-3.25) 35(4.4,-2.75) 36(4.4,-2.25) 37(4.4,-1.75) 38(4.4,-1.25) 39(4.4,-0.75) 40(4.4,-0.25) 41(4.4,0.25) 42(4.4,0.75) 43(4.4,1.25) 44(4.4,1.75) 45(4.4,2.25) 46(4.4,2.75) 47(4.4,3.25) 48(4.4,3.75)
  rrect42% 0.24x0.6 smd: 17(-3.75,-4.4) 18(-3.25,-4.4) 19(-2.75,-4.4) 20(-2.25,-4.4) 21(-1.75,-4.4) 22(-1.25,-4.4) 23(-0.75,-4.4) 24(-0.25,-4.4) 25(0.25,-4.4) 26(0.75,-4.4) 27(1.25,-4.4) 28(1.75,-4.4) 29(2.25,-4.4) 30(2.75,-4.4) 31(3.25,-4.4) 32(3.75,-4.4) 49(3.75,4.4) 50(3.25,4.4) 51(2.75,4.4) 52(2.25,4.4) 53(1.75,4.4) 54(1.25,4.4) 55(0.75,4.4) 56(0.25,4.4) 57(-0.25,4.4) 58(-0.75,4.4) 59(-1.25,4.4) 60(-1.75,4.4) 61(-2.25,4.4) 62(-2.75,4.4) 63(-3.25,4.4) 64(-3.75,4.4)
  rrect10% 1x1 on Top Paste: 65(-2.4,-2.4) 65(-2.4,-1.2) 65(-2.4,0) 65(-2.4,1.2) 65(-2.4,2.4) 65(-1.2,-2.4) 65(-1.2,-1.2) 65(-1.2,0) 65(-1.2,1.2) 65(-1.2,2.4) 65(0,-2.4) 65(0,-1.2) 65(0,0) 65(0,1.2) 65(0,2.4) 65(1.2,-2.4) 65(1.2,-1.2) 65(1.2,0) 65(1.2,1.2) 65(1.2,2.4) 65(2.4,-2.4) 65(2.4,-1.2) 65(2.4,0) 65(2.4,1.2) 65(2.4,2.4)
  rrect2% 6.3x6.3 smd paste-4: 65(0,0)
  silkscreen extent -4.7,-4.7 4.7,4.7, body extent -4.5,-4.5 4.5,4.5, height 1
RGZ0048A [mm] "VQFN-48"
  rrect42% 0.6x0.24 smd: 1(-3.4,2.75) 2(-3.4,2.25) 3(-3.4,1.75) 4(-3.4,1.25) 5(-3.4,0.75) 6(-3.4,0.25) 7(-3.4,-0.25) 8(-3.4,-0.75) 9(-3.4,-1.25) 10(-3.4,-1.75) 11(-3.4,-2.25) 12(-3.4,-2.75) 25(3.4,-2.75) 26(3.4,-2.25) 27(3.4,-1.75) 28(3.4,-1.25) 29(3.4,-0.75) 30(3.4,-0.25) 31(3.4,0.25) 32(3.4,0.75) 33(3.4,1.25) 34(3.4,1.75) 35(3.4,2.25) 36(3.4,2.75)
  rrect42% 0.24x0.6 smd: 13(-2.75,-3.4) 14(-2.25,-3.4) 15(-1.75,-3.4) 16(-1.25,-3.4) 17(-0.75,-3.4) 18(-0.25,-3.4) 19(0.25,-3.4) 20(0.75,-3.4) 21(1.25,-3.4) 22(1.75,-3.4) 23(2.25,-3.4) 24(2.75,-3.4) 37(2.75,3.4) 38(2.25,3.4) 39(1.75,3.4) 40(1.25,3.4) 41(0.75,3.4) 42(0.25,3.4) 43(-0.25,3.4) 44(-0.75,3.4) 45(-1.25,3.4) 46(-1.75,3.4) 47(-2.25,3.4) 48(-2.75,3.4)
  rrect2% 5.15x5.15 smd paste-2.6: 49(0,0)
  body extent -3.5,-3.5 3.5,3.5, height 1
Richwave_RTC6608OSP [mm] "SMD, 6-Leads, Body 1x1mm"
  rrect67% 0.45x0.15 smd: 1(-0.5,0.35) 3(-0.5,-0.35) 4(0.5,-0.35) 5(0.5,0) 6(0.5,0.35)
  rrect100% 0.1x0.1 smd: 2(-0.5,0)
  Top Layer region: -0.725,-0.076 -0.725,-0.076 -0.726,-0.076 -0.726,-0.075 -0.726,-0.075 -0.726,-0.075 -0.726,0.075 -0.726,0.075 -0.726,0.076 -0.725,0.076 -0.725,0.076 -0.725,0.076 -0.275,0.076 -0.101,0.225 -0.101,0.5 -0.101,0.5 -0.101,0.501 -0.1,0.501 -0.1,0.501 -0.1,0.501 0.1,0.501 0.1,0.501 0.101,0.501 0.101,0.5 0.101,0.5 0.101,0.5 0.101,0.226 0.15,0.226 0.15,0.226 0.151,0.226 0.151,0.225 0.151,0.225 0.151,0.225 0.151,-0.225 0.151,-0.225 0.151,-0.226 0.15,-0.226 0.15,-0.226 0.15,-0.226 0.101,-0.226 0.101,-0.5 0.101,-0.5 0.101,-0.501 0.1,-0.501 0.1,-0.501 0.1,-0.501 -0.1,-0.501 -0.1,-0.501 -0.101,-0.501 -0.101,-0.5 -0.101,-0.5 -0.101,-0.5 -0.101,-0.225 -0.275,-0.076
  silkscreen extent -1.05,0.45 -0.95,0.55, body extent -0.55,-0.55 0.55,0.55, height 0.41
Samtec_FTSH-105-01-x-DV-K [mm] "Header(Shrouded), 1.27mm, 5x2, SMT"
  rect 2.79x0.74 smd: 1(-2.035,2.54) 2(2.035,2.54) 3(-2.035,1.27) 4(2.035,1.27) 5(-2.035,0) 6(2.035,0) 7(-2.035,-1.27) 8(2.035,-1.27) 9(-2.035,-2.54) 10(2.035,-2.54)
  silkscreen extent -3.73,-3.48 3.73,3.48, body extent -2.92,-3.18 2.92,3.17, height 6.13
SOT-23 [mm] "SOT23, 3-Leads, Body 2.9x1.3mm, Pitch 0.95mm, Lead Span 2.5mm, IPC Medium Density"
  rrect50% 1x0.6 smd: 1(-1.2,0.95) 2(-1.2,-0.95) 3(1.2,0)
  silkscreen extent -1.63,-1.5 0.7,1.5, body extent -1.16,-1.45 1.21,1.45, height 1
Sullins_Gxx02SAAN [mm] "Header, 2.54 mm, 2x1, TH"
  rect 1.55x1.55 hole 1.016: 1(-1.27,0)
  round 1.55 hole 1.016: 2(1.27,0)
  silkscreen extent -2.54,-1.75 2.54,1.27, body extent -2.54,-1.27 2.54,1.27, height 8.38
SW_1188E [mm] "SMD, 4-Leads, Body 7.8x3.5mm"
  rrect10% 1x1.45 smd: 1(-1.1,3.375) 2(-1.1,-3.375)
  rrect11% 1.3x0.9 smd: 3(0.7,2.1) 4(0.7,-2.1)
  round 0 hole 0.9 unplated: ""(-0.35,1.15) ""(-0.35,-1.15)
  silkscreen extent -1.97,-2.28 0.95,2.28, body extent -2.55,-3.9 1.05,3.9, height 3.5
TAYO_AH316M [mm] "SMD, 2-Leads, Body 3.2x1.6mm"
  rect 1x1.2 smd: 1(-1.6,0) 2(1.6,0)
  silkscreen extent -2.73,-0.87 0.9,0.88, body extent -1.68,-0.87 1.68,0.88, height 0.61
TDK_DEA202450BT-1294C1-H [mm] "SMD, 4-Leads, Body 2x1.25mm"
  rect 0.35x0.35 smd: 1(0,0.325) 3(0,-0.325)
  rect 0.45x1 smd: 2(0.65,0) 4(-0.65,0)
  silkscreen extent -1.18,-0.8 1.17,1, body extent -1.07,-0.68 1.07,0.68, height 0.8
Testpoint_Keystone_Miniature [mil] "Miniature SMT test point"
  rect 135x70 smd: 1(0,0)
  silkscreen extent -78,-46 78,45, body extent -52,-20 52,20, height 61
TI_Stacked_Overlay_Small [mil]
  silkscreen extent -418,-98 418,98
TXC_8Y [mm] "SMD, 4-Leads, Body 2x1.6mm"
  rect 0.8x0.9 smd: 1(-0.55,0.7) 2(-0.55,-0.7) 3(0.55,-0.7) 4(0.55,0.7)
  silkscreen extent -0.61,1.41 -0.49,1.54, body extent -0.85,-1.05 0.85,1.05, height 0.56
WEEE_Minimum [mil] "WEEElie bin"
WL-SMCW_YELLOW [mm] "WURTH"
  rect 0.8x0.8 smd: 1(-0.8,0) 2(0.8,0)
  silkscreen extent -1.9,-0.8 1.2,0.8, body extent -0.85,-0.45 0.85,0.45, height 0.8
Wurth_60900213421 [mil] "Shunt, 2.54mm, Black"
  round 1 on Mech3: 0(0,0)
  body extent -98,-48 98,48, height 338
WURTH_61300311121 [mm] "Header, 2.54mm, 3x1, TH"
  rrect50% 1.65x1.65 hole 1.15: 1(-2.54,0)
  round 1.65 hole 1.15: 2(0,0) 3(2.54,0)
  body extent -3.81,-1.27 3.81,1.27, height 8.54
Wurth_61300511121 [mm] "Header, 2.54mm, 5x1, TH"
  rrect50% 1.65x1.65 hole 1.1: 1(-5.08,0)
  round 1.65 hole 1.1: 2(-2.54,0) 3(0,0) 4(2.54,0) 5(5.08,0)
  body extent -6.35,-1.27 6.35,1.27, height 8.54
Wurth_61300621121 [mm] "Header, 2.54mm, 3x2, TH"
  rect 1.6x1.6 hole 1.1: 1(-1.27,2.54)
  round 1.6 hole 1.1: 2(1.27,2.54) 3(-1.27,0) 4(1.27,0) 5(-1.27,-2.54) 6(1.27,-2.54)
  silkscreen extent -2.8,-3.82 2.54,3.8, body extent -2.54,-3.82 2.54,3.8, height 7.27
XTAL_ABS07 [mm] "ABRACON"
  rect 1.1x1.9 smd: 1(-1.25,0) 2(1.25,0)
  silkscreen extent -0.4,-1 0.4,1, body extent -1.65,-0.8 1.65,0.8, height 0.9

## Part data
C1 C2: library part CMP-0007405-4, "CAP, CERM, 1 uF, 25 V, +/- 10%, X7R, 0603", Cap_Case=0603, Manufacturer=MuRata, Supplier Part Number 1=490-5307-1-ND, TempCo=X7R, Tolerance_%=10%, Value1=Unknown, Value2=25V, ValueDisplayed=1uF
C3: library part CMP-0006723-4, "CAP, CERM, 1000 pF, 100 V, +/- 5%, X7R, 0603", Cap_Case=0603, Manufacturer=AVX, Supplier Part Number 1=478-3698-1-ND, TempCo=X7R, Tolerance_%=5%, Value1="0.276 ohm", Value2=100V, ValueDisplayed=1000pF
C4: library part CMP-0006292-2, "CAP, CERM, 0.01 uF, 16 V, +/- 10%, X7R, 0402", Alternate Manufacturer=Walsin, Alternate PartNumber=0402B103K500CT, Cap_Case=0402, Manufacturer=TDK, Supplier Part Number 1=445-1262-1-ND, TempCo=X7R, Tolerance_%=10%, Value1="0.0623 ohm", Value2=16V, ValueDisplayed=0.01uF
C5 C14 C34 C35 C36 C38 C40 C41: library part CMP-0064970-1, "CAP, CERM, 0.1 uF, 16 V,+/- 10%, X7R, 0201", Cap_Case=0201, Manufacturer=MuRata, Supplier Part Number 1=81-GRM033Z71C104KE4D, TempCo=X7R, Tolerance_%=10%, Value1=Unknown, Value2=16V, ValueDisplayed=0.1uF
C6: library part CMP-0085842-1, "CAP, CERM, 0.01 µF, 50 V,+/- 10%, X7R, 0402", Alternate PartNumber=GRM155R71E103KA01D, Cap_Case=0402, Manufacturer=Walsin, TempCo=X7R, Tolerance_%=10%, Value2=50V, ValueDisplayed=0.01µF
C7 C8 C10: "CAP, CERM, 4.7 uF, 6.3 V,+/- 20%, X6S, 0402", Alternate Manufacturer=SAMSUNG, Alternate PartNumber=CL05A475MQ5NRNC, Cap_Case=0402, Manufacturer="Taiyo Yuden", PartNumber=JMK105BC6475MV-F, Supplier Part Number 1=48Y4404, TempCo=X6S, Tolerance_%=20%, Value1=Unknown, Value2=6.3V, ValueDisplayed=4.7uF
C9 C19 C32: library part CMP-0085407-1, "CAP, CERM, 0.6pF, 25 V,+/- 16%, C0G/NP0, 0201", Cap_Case=0201, Manufacturer=MuRata, TempCo=C0G/NP0, Tolerance_%=16%, Value2=25V, ValueDisplayed=0.6pF
C11: library part CMP-0085408-2, "CAP, CERM, 0.5 pF, 25 V,+/- 20%, C0G/NP0, 0201", Cap_Case=0201, Manufacturer=MuRata, TempCo=C0G/NP0, Tolerance_%=20%, Value2=25V, ValueDisplayed=0.5pF
C12 C13 C16 C24 C25 C27: library part CMP-0085850-1, "CAP, CERM, 0.1 µF, 16 V,+/- 10%, X7R, 0402", Alternate PartNumber=C1005X5R1A104K050BA, Cap_Case=0402, Manufacturer=Walsin, TempCo=X7R, Tolerance_%=10%, Value2=16V, ValueDisplayed=0.1µF
C15 C23 C26: "CAP, CERM, 10 uF, 10 V,+/- 20%, X6S, 0603", Alternate Manufacturer=SAMSUNG, Alternate PartNumber=CL10A106MP8NNNC, Cap_Case=0603, Manufacturer="Taiyo Yuden", PartNumber=LMK107BC6106MA-T, Supplier Part Number 1=95Y1652, TempCo=X6S, Tolerance_%=20%, Value1=Unknown, Value2=10V, ValueDisplayed=10uF
C17: library part CMP-0085602-1, "CAP, CERM, 0.2pF, 25 V,+/- 50%, C0G/NP0, 0201", Cap_Case=0201, Manufacturer=MuRata, TempCo=C0G/NP0, Tolerance_%=50%, Value2=25V, ValueDisplayed=0.2pF
C18: library part CMP-0009655-3, "CAP, CERM, 0.1 uF, 10 V, +/- 10%, X5R, 0201", Cap_Case=0201, Manufacturer="Samsung Electro-Mechanics", TempCo=X5R, Tolerance_%=10%, Value1=Unknown, Value2=10V, ValueDisplayed=0.1uF
C20 C21: "CAP, CERM, 22 uF, 4 V,+/- 20%, X6S, 0603", Alternate Manufacturer=SAMSUNG, Alternate PartNumber=CL10A226MQ8NRNC, Cap_Case=0603, Manufacturer=MuRata, PartNumber=GRM188C80G226ME15J, Supplier Part Number 1=81-GRM188C80G226ME5J, TempCo=X6S, Tolerance_%=20%, Value1=Unknown, Value2=4V, ValueDisplayed=22uF
C22: library part CMP-0085849-1, "CAP, CERM, 1 µF, 10 V,+/- 20%, X5R, 0402", Alternate PartNumber=GRM155C81A105KA12D, Cap_Case=0402, Manufacturer=Walsin, TempCo=X5R, Tolerance_%=20%, Value2=10V, ValueDisplayed=1µF
C28: "CAP, CERM, 0.1 uF, 10 V, +/- 10%, X5R, 0201", Cap_Case=0201, Manufacturer="Samsung Electro-Mechanics", PartNumber=CL03A104KP3NNNC, TempCo=X5R, Tolerance_%=10%, Value1=Unknown, Value2=10V, ValueDisplayed=0.1uF
C29 C30: library part CMP-0085843-1, "CAP, CERM, 10 pF, 50 V,+/- 5%, C0G/NP0, 0402", Alternate PartNumber=GRM1555C1H100JA01D, Cap_Case=0402, Manufacturer=Walsin, TempCo=C0G/NP0, Tolerance_%=5%, Value2=50V, ValueDisplayed=10pF
C31 C33: library part CMP-0085844-1, "CAP, CERM, 6.2 pF, 50 V,+/- 4%, C0G/NP0, 0402", Alternate PartNumber=GRM1555C1H6R2CA01D, Cap_Case=0402, Manufacturer=Walsin, TempCo=C0G/NP0, Tolerance_%=4%, Value2=50V, ValueDisplayed=6.2pF
C37 C39: library part CMP-0006545-2, "CAP, CERM, 22 uF, 6.3 V, +/- 20%, X5R, 0402", Cap_Case=0402, Manufacturer=MuRata, TempCo=X5R, Tolerance_%=20%, Value1=Unknown, Value2=6.3V, ValueDisplayed=22uF
C42 C43: library part CMP-0009633-3, "CAP, CERM, 12 pF, 25 V, +/- 5%, C0G/NP0, 0201", Cap_Case=0201, Manufacturer=TDK, Supplier Part Number 1=445-4653-1-ND, TempCo=C0G/NP0, Tolerance_%=5%, Value1="0 ohm", Value2=25V, ValueDisplayed=12pF
C44: library part CMP-0089441-1, "1µF ±20% 6.3V Ceramic Capacitor X6S 0201 (0603 Metric)", Digikey Part Number=587-6143-1-ND, Manufacturer="Taiyo Yuden", Mouser Part Number=963-JMK063BC6105MP-F, Operating Temperature Range="-55°C to +105°C", TempCo=22%, Temperature Characteristic=X6S, Tolerance_%=20%, ValueDisplayed=1uF
C45 C48: "CAP, CERM, 8.2 pF, 50 V, +/- 5%, C0G/NP0, 0402", Alternate Manufacturer=Walsin, Alternate PartNumber=0402N8R2C500CT, Cap_Case=0402, Manufacturer=MuRata, PartNumber=GRM1555C1H8R2CA01D, Supplier Part Number 1=14T3299, TempCo=C0G/NP0, Tolerance_%=5%, Value1=Unknown, Value2=50V, ValueDisplayed=8.2pF
C46 C49: "CAP, CERM, 2.2 pF, 50 V, +/- 5%, C0G/NP0, 0402", Alternate Manufacturer=----, Cap_Case=0402, Manufacturer=MuRata, PartNumber=GRM1555C1H2R2BA01D, Supplier Part Number 1=490-6227-1-ND, TempCo=C0G/NP0, Tolerance_%=5%, Value1=Unknown, Value2=50V, ValueDisplayed=2.2pF
C47 C50: "CAP, CERM, 1 pF, 50 V, +/- 10%, C0G/NP0, 0402", Alternate Manufacturer=----, Cap_Case=0402, Manufacturer=MuRata, PartNumber=GRM1555C1H1R0BA01D, Supplier Part Number 1=490-6206-1-ND, TempCo=C0G/NP0, Tolerance_%=10%, Value1=Unknown, Value2=50V, ValueDisplayed=1pF
D1: library part CMP-0086159-1, "LED, Red, SMD", Color=Red, Manufacturer=Everlight, Power_TotalModule=60mW, Value1=0.06W, Value2=1.95V
D2: library part CMP-0003017-3, "LED, RGB, SMD", Color=RGB, Manufacturer=Everlight, Value2=3.7V
D3 D4: library part CMP-0002892-3, "LED, Yellow, SMD", Color=yellow, Manufacturer="Wurth Elektronik", Value1=W, Value2=2V
E1: library part CMP-0002031-2, "ANT BLUETOOTH W-LAN ZIGBEE WIMAX, SMD", Manufacturer="Taiyo Yuden", Supplier Part Number 1=587-2200-1-ND
FID1 FID2 FID3: "Fiducial mark.  There is nothing to buy or mount.", Manufacturer=N/A
FL1: library part CMP-0001890-2, "2.4GHz Impedance Matched Balun + embedded FCC/ETSI Band Pass Filter, SMD", Manufacturer="Johanson Technology"
FL2: "Multilayer Chip Band Pass Filter For 2.4GHz W-LAN/Bluetooth, SMD", Alternate Manufacturer=----, Manufacturer=TDK, PartNumber=DEA202450BT-1294C1-H, Supplier Part Number 1=445-172335-1-ND
H2 H3 H4 H5: library part CMP-0003617-1, "Machine Screw, Round, #4-40 x 1/4, Nylon, Philips panhead", Manufacturer="B&F Fastener Supply", Supplier Part Number 1=H542-ND
H6 H7 H8 H9: library part CMP-0003610-1, "Standoff, Hex, 0.5\"L #4-40 Nylon", Manufacturer=Keystone, PartNumber=1902C, Supplier Part Number 1=36-1902C-ND
J1 J2: library part CMP-0075670-2, "Header (Shrouded), 1.27mm, 5x2, Gold, SMT", Color=Black, Current_A=3.3A, Manufacturer=Samtec, Supplier Part Number 1=SAM8796-ND
J3: library part CMP-0055311-1, "Receptacle, USB 2.0, Micro B, 5 Position, R/A, SMT", Color=Black, Current_A=1.8A, Manufacturer=Molex, Supplier Part Number 1=WM11263CT-ND, Voltage_V=30V
J4 J5: library part CMP-0054576-1, "Header, 2.54 mm, 2x1, Gold, TH", Manufacturer="Sullins Connector Solutions"
J6: library part CMP-0084909-1, "Header, 2.54mm, 5x1, Gold, TH", Color=Black, Current_A=3A, Manufacturer="Wurth Elektronik", Voltage_V=250V
J7 J8 J9: library part CMP-0054796-2, "Header, 2.54 mm, 3x1, Gold, TH", Color=Black, Manufacturer="Wurth Elektronik", Supplier Part Number 1=732-5316-ND
J10: library part CMP-0054802-2, "Header, 2.54mm, 3x2, Gold, TH", Color=Black, Manufacturer="Wurth Elektronik", Supplier Part Number 1=732-5295-ND
J11: "Connector, SMA, Vertical, Gold, SMT", Alternate Manufacturer=??, Alternate PartNumber=SMA-050710, Manufacturer="Hus-Tsan Group Co., Ltd.", PartNumber=SMA-10V21-TGG
L1 L2: "Ferrite Bead, 10 ohm @ 100 MHz, 1 A, 0402", Alternate Manufacturer=----, Manufacturer=MuRata, PartNumber=BLM15AG100SN1D, Supplier Part Number 1=490-5176-1-ND, Value1="0.025 ohm", Value2=1A, ValueDisplayed="10 ohm"
L3 L5: "Inductor, Multilayer, Ferrite, 2.2 uH, 1.2 A, 0.11 ohm, SMD", Alternate Manufacturer=----, Manufacturer=MuRata, PartNumber=LQM2MPN2R2NG0, Supplier Part Number 1=490-7786-1-ND, Value1="0.11 ohm", Value2=1.2A, ValueDisplayed=2.2uH
L4: "Inductor, Multilayer, Ferrite, 1 uH, 1.6 A, 0.055 ohm, SMD", Alternate Manufacturer=----, Manufacturer=MuRata, PartNumber=LQM2HPN1R0MG0L, Supplier Part Number 1=490-5112-1-ND, Value1="0.055 ohm", Value2=1.6A, ValueDisplayed=1uH
L6: "Inductor, Multilayer, Ferrite, 10 uH, 0.7 A, 0.364 ohm, SMD", Alternate Manufacturer=----, Manufacturer=TDK, PartNumber=MLP2520S100MT0S1, Supplier Part Number 1=445-9504-1-ND, Value1="0.364 ohm", Value2=0.7A, ValueDisplayed=10uH
L7: library part CMP-0062727-1, "Inductor, Multilayer, Ferrite, 6.8 uH, 0.11 A, 0.25 ohm, SMD", Manufacturer=TDK, Supplier Part Number 1=445-6761-1-ND, Value1="0.25 ohm", Value2=0.11A, ValueDisplayed=6.8uH
L8: library part CMP-0003349-2, "Ferrite Bead, 1500 ohm @ 100 MHz, 0.5 A, 0603", Manufacturer=MuRata, Supplier Part Number 1=490-5216-1-ND, Value1="0.5 ohm", Value2=0.5A, ValueDisplayed="1500 ohm"
L9 L10: library part CMP-0058633-2, "Inductor, Multilayer, Air Core, 3.9 nH, 0.75 A, 0.14 ohm, SMD", Manufacturer=MuRata, Supplier Part Number 1=490-2617-1-ND, Value1="0.14 ohm", Value2=0.75A, ValueDisplayed=3.9nH
Label1: "Thermal Transfer Printable Labels, 0.650\" W x 0.200\" H - 10,000 per roll", Alternate Manufacturer=----, Manufacturer=Brady, PartNumber=THT-14-423-10, Supplier Part Number 1=97C5133
Logo1: library part CMP-0074838-1, "Texas Instrument Corporate Signature"
Logo2: library part CMP-0074769-1
Logo3: library part CMP-0074847-1, "FCC_disclaimer"
Logo4: library part CMP-0074840-1, "ESD Susceptible Symbol"
Q1 Q2: "MOSFET, N-CH, 50 V, 0.22 A, SOT-23", Alternate Manufacturer=ON, Alternate PartNumber=BSS138LT1G, Manufacturer="Fairchild Semiconductor", PartNumber=BSS138, Supplier Part Number 1=BSS138CT-ND, Value2="1.7 nC"
Q3 Q4 Q5: library part CMP-0000755-1, "MOSFET, N-CH, 50 V, 0.22 A, SOT-23", Alternate Manufacturer=None, Manufacturer="Fairchild Semiconductor", Supplier Part Number 1=BSS138CT-ND, Value2="1.7 nC"
R1: library part CMP-0026852-3, "RES, 1.0 k, 5%, 0.063 W, AEC-Q200 Grade 0, 0402", Manufacturer=Vishay-Dale, Power_W=63mW, Supplier Part Number 1=541-1.0KJCT-ND, TempCo="200 ppm/C", Tolerance_%=5%, Value2=0.063W, Value_Code=1k00, ValueDisplayed=1.0k
R2 R6 R7: "RES, 270, 5%, 0.1 W, AEC-Q200 Grade 0, 0603", Alternate Manufacturer=YAGEO, Alternate PartNumber=RC0603JR-07270RL, Manufacturer=Vishay-Dale, PartNumber=CRCW0603270RJNEA, Power_W=100mW, Supplier Part Number 1=541-270GCT-ND, TempCo="200 ppm/C", Tolerance_%=5%, Value2=0.1W, Value_Code=270R, ValueDisplayed=270
R3: "RES, 100 k, 5%, 0.1 W, AEC-Q200 Grade 0, 0603", Alternate Manufacturer=YAGEO, Alternate PartNumber=RC0603JR-07100KL, Manufacturer=Vishay-Dale, PartNumber=CRCW0603100KJNEA, Power_W=100mW, Supplier Part Number 1=541-100KGCT-ND, TempCo="200 ppm/C", Tolerance_%=5%, Value2=0.1W, Value_Code=100k
R4 R5: "RES, 1.0 k, 5%, 0.063 W, AEC-Q200 Grade 0, 0402", Alternate Manufacturer=YAGEO, Alternate PartNumber=RC0402JR-071KL, Manufacturer=Vishay-Dale, PartNumber=CRCW04021K00JNED, Power_W=63mW, Supplier Part Number 1=541-1.0KJCT-ND, TempCo="200 ppm/C", Tolerance_%=5%, Value2=0.063W, Value_Code=1k00, ValueDisplayed=1.0k
R8 R22 R23 R24 R25 R26 R35 R36: library part CMP-0027184-1, "RES, 100 k, 5%, 0.05 W, 0201", Manufacturer="Yageo America", Power_W=50mW, Supplier Part Number 1=603-RC0201JR-7D100KL, TempCo="200 ppm/C", Tolerance_%=5%, Value2=0.05W, Value_Code=100k
R9 R10 R11: library part CMP-0025939-5, "RES, 750, 5%, 0.1 W, 0603", Manufacturer=Yageo, Power_W=100mW, Supplier Part Number 1=311-750GRCT-ND, TempCo="100 ppm/C", Tolerance_%=5%, Value2=0.1W, Value_Code=750R, ValueDisplayed=750
R12 R13: "RES, 10 k, 5%, 0.063 W, AEC-Q200 Grade 0, 0402", Alternate Manufacturer=YAGEO, Alternate PartNumber=RC0402JR-0710KL, Manufacturer=Vishay-Dale, PartNumber=CRCW040210K0JNED, Power_W=63mW, Supplier Part Number 1=541-10KJCT-ND, TempCo="200 ppm/C", Tolerance_%=5%, Value2=0.063W, Value_Code=10k0, ValueDisplayed=10k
